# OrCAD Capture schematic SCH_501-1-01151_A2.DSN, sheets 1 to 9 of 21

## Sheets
1 P01_COVER_PAGE
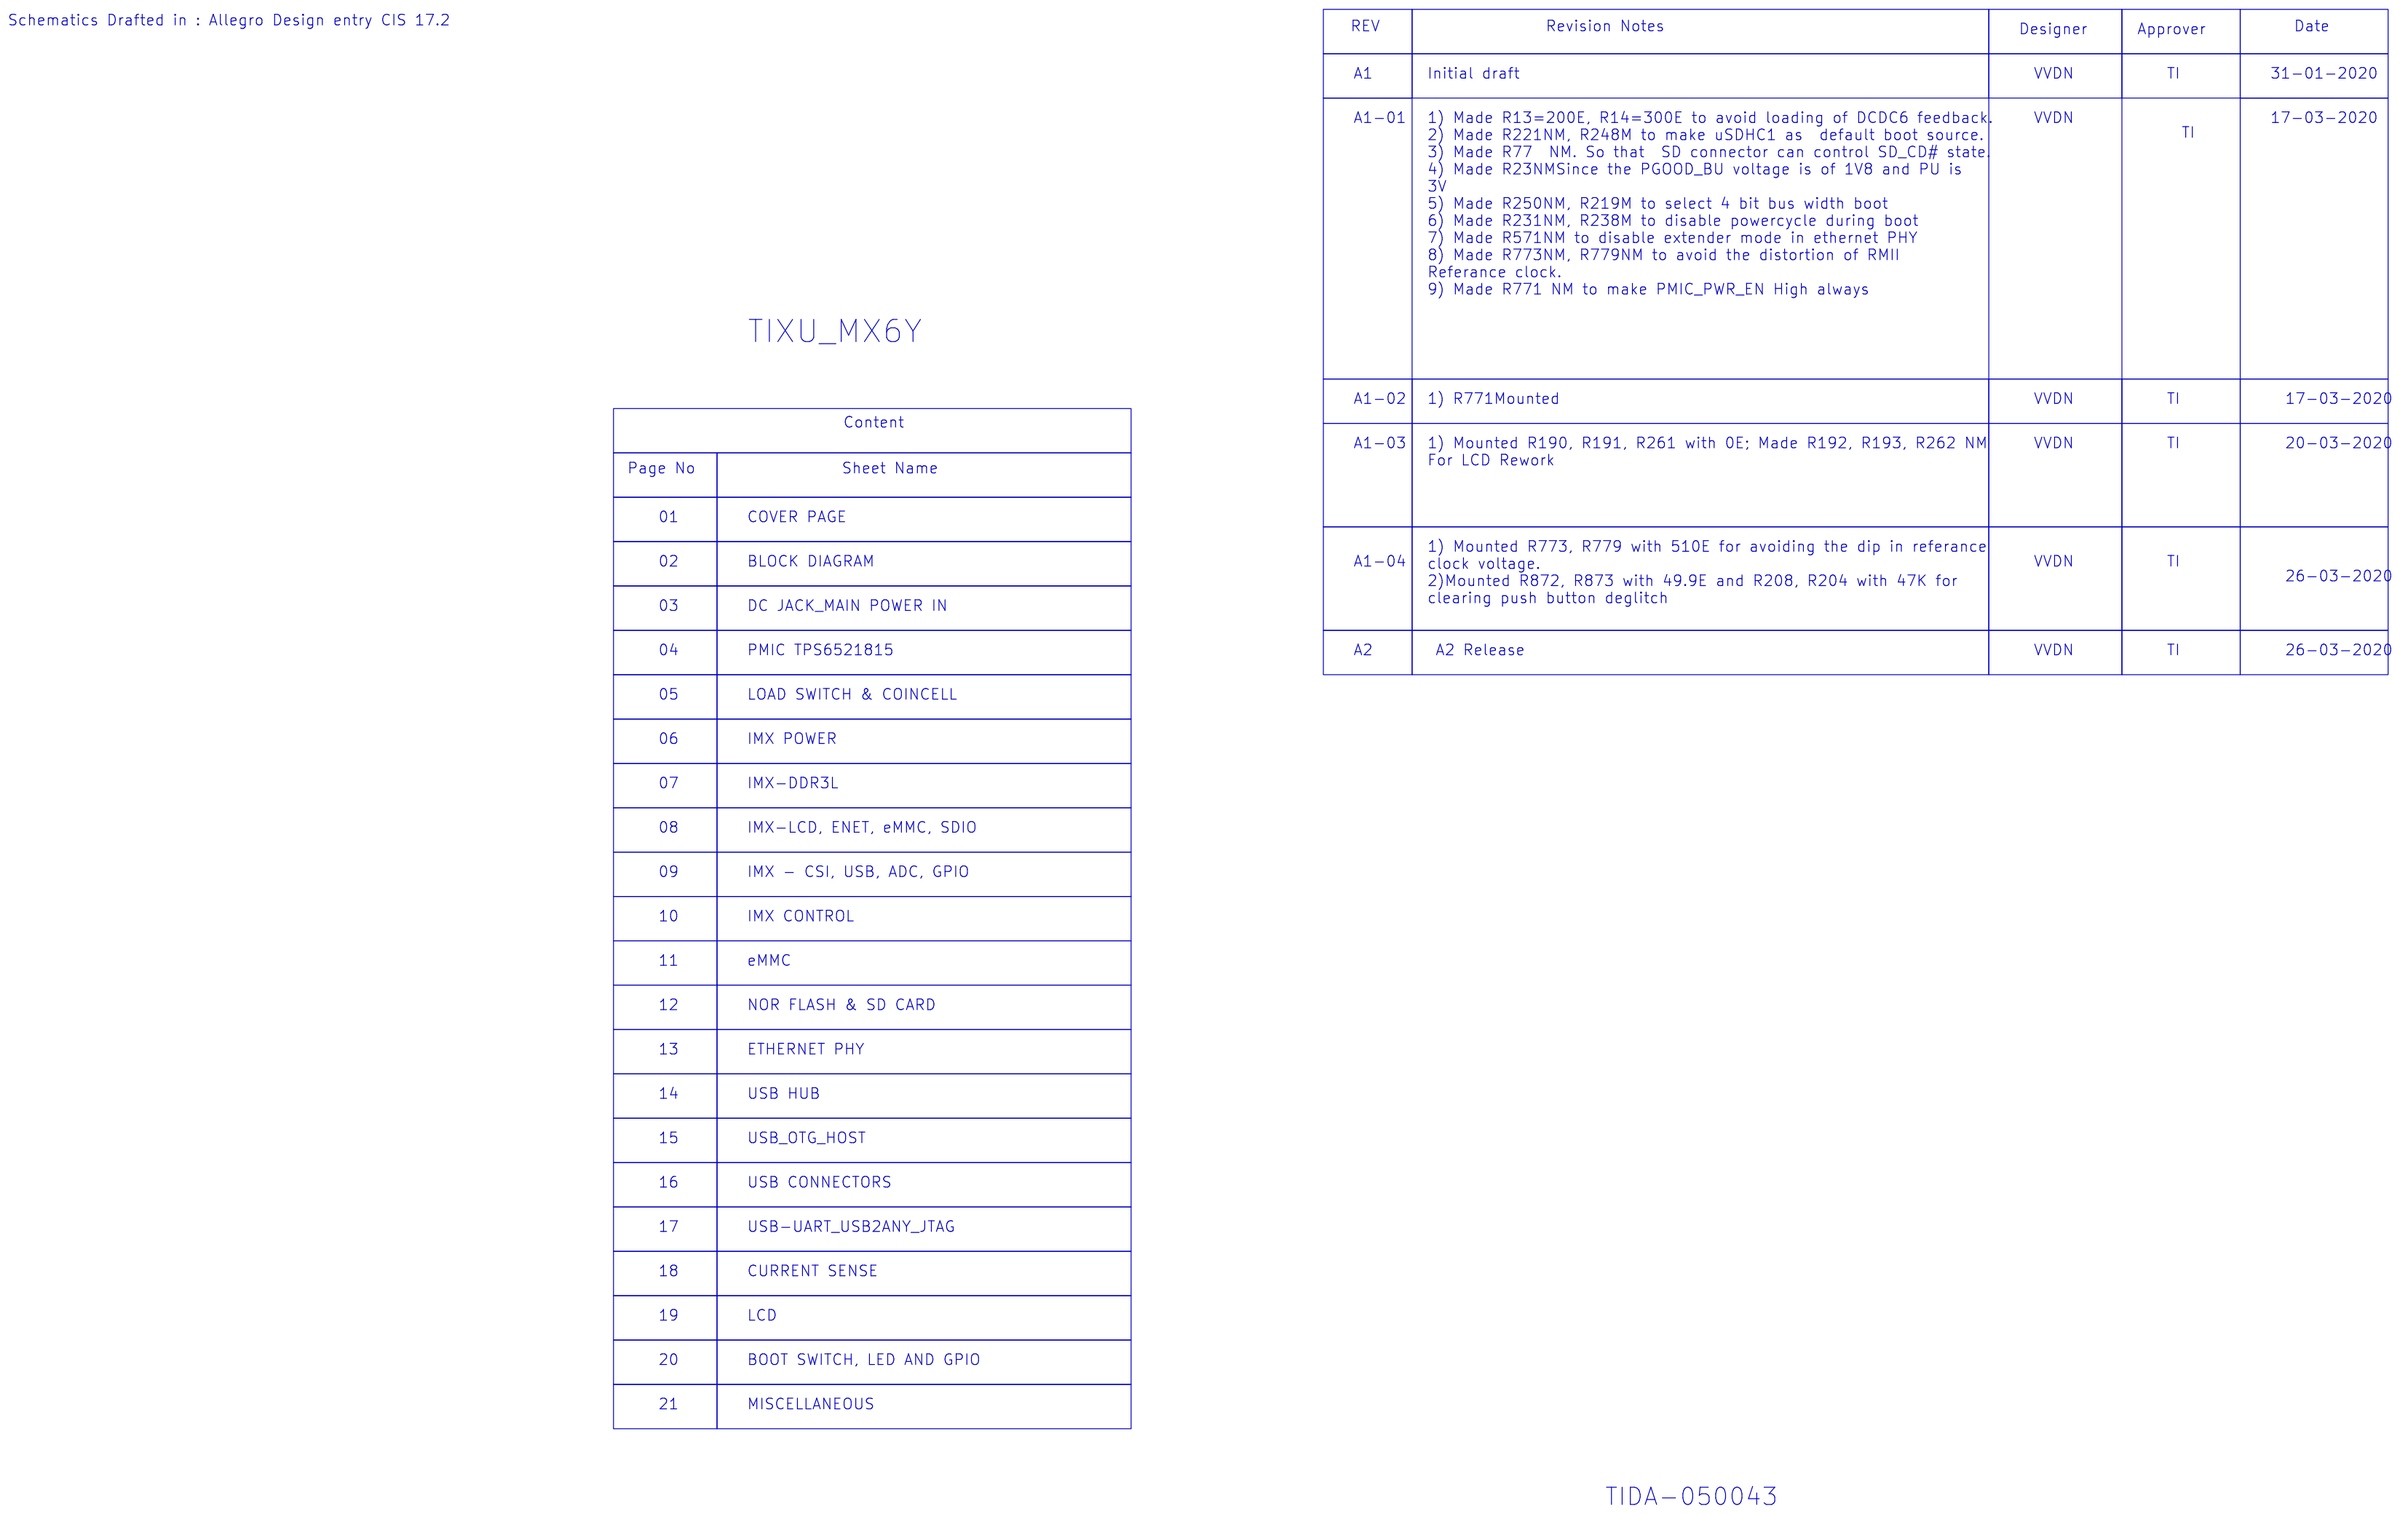
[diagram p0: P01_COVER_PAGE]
2 P02_BLOCK_DIAGRAM
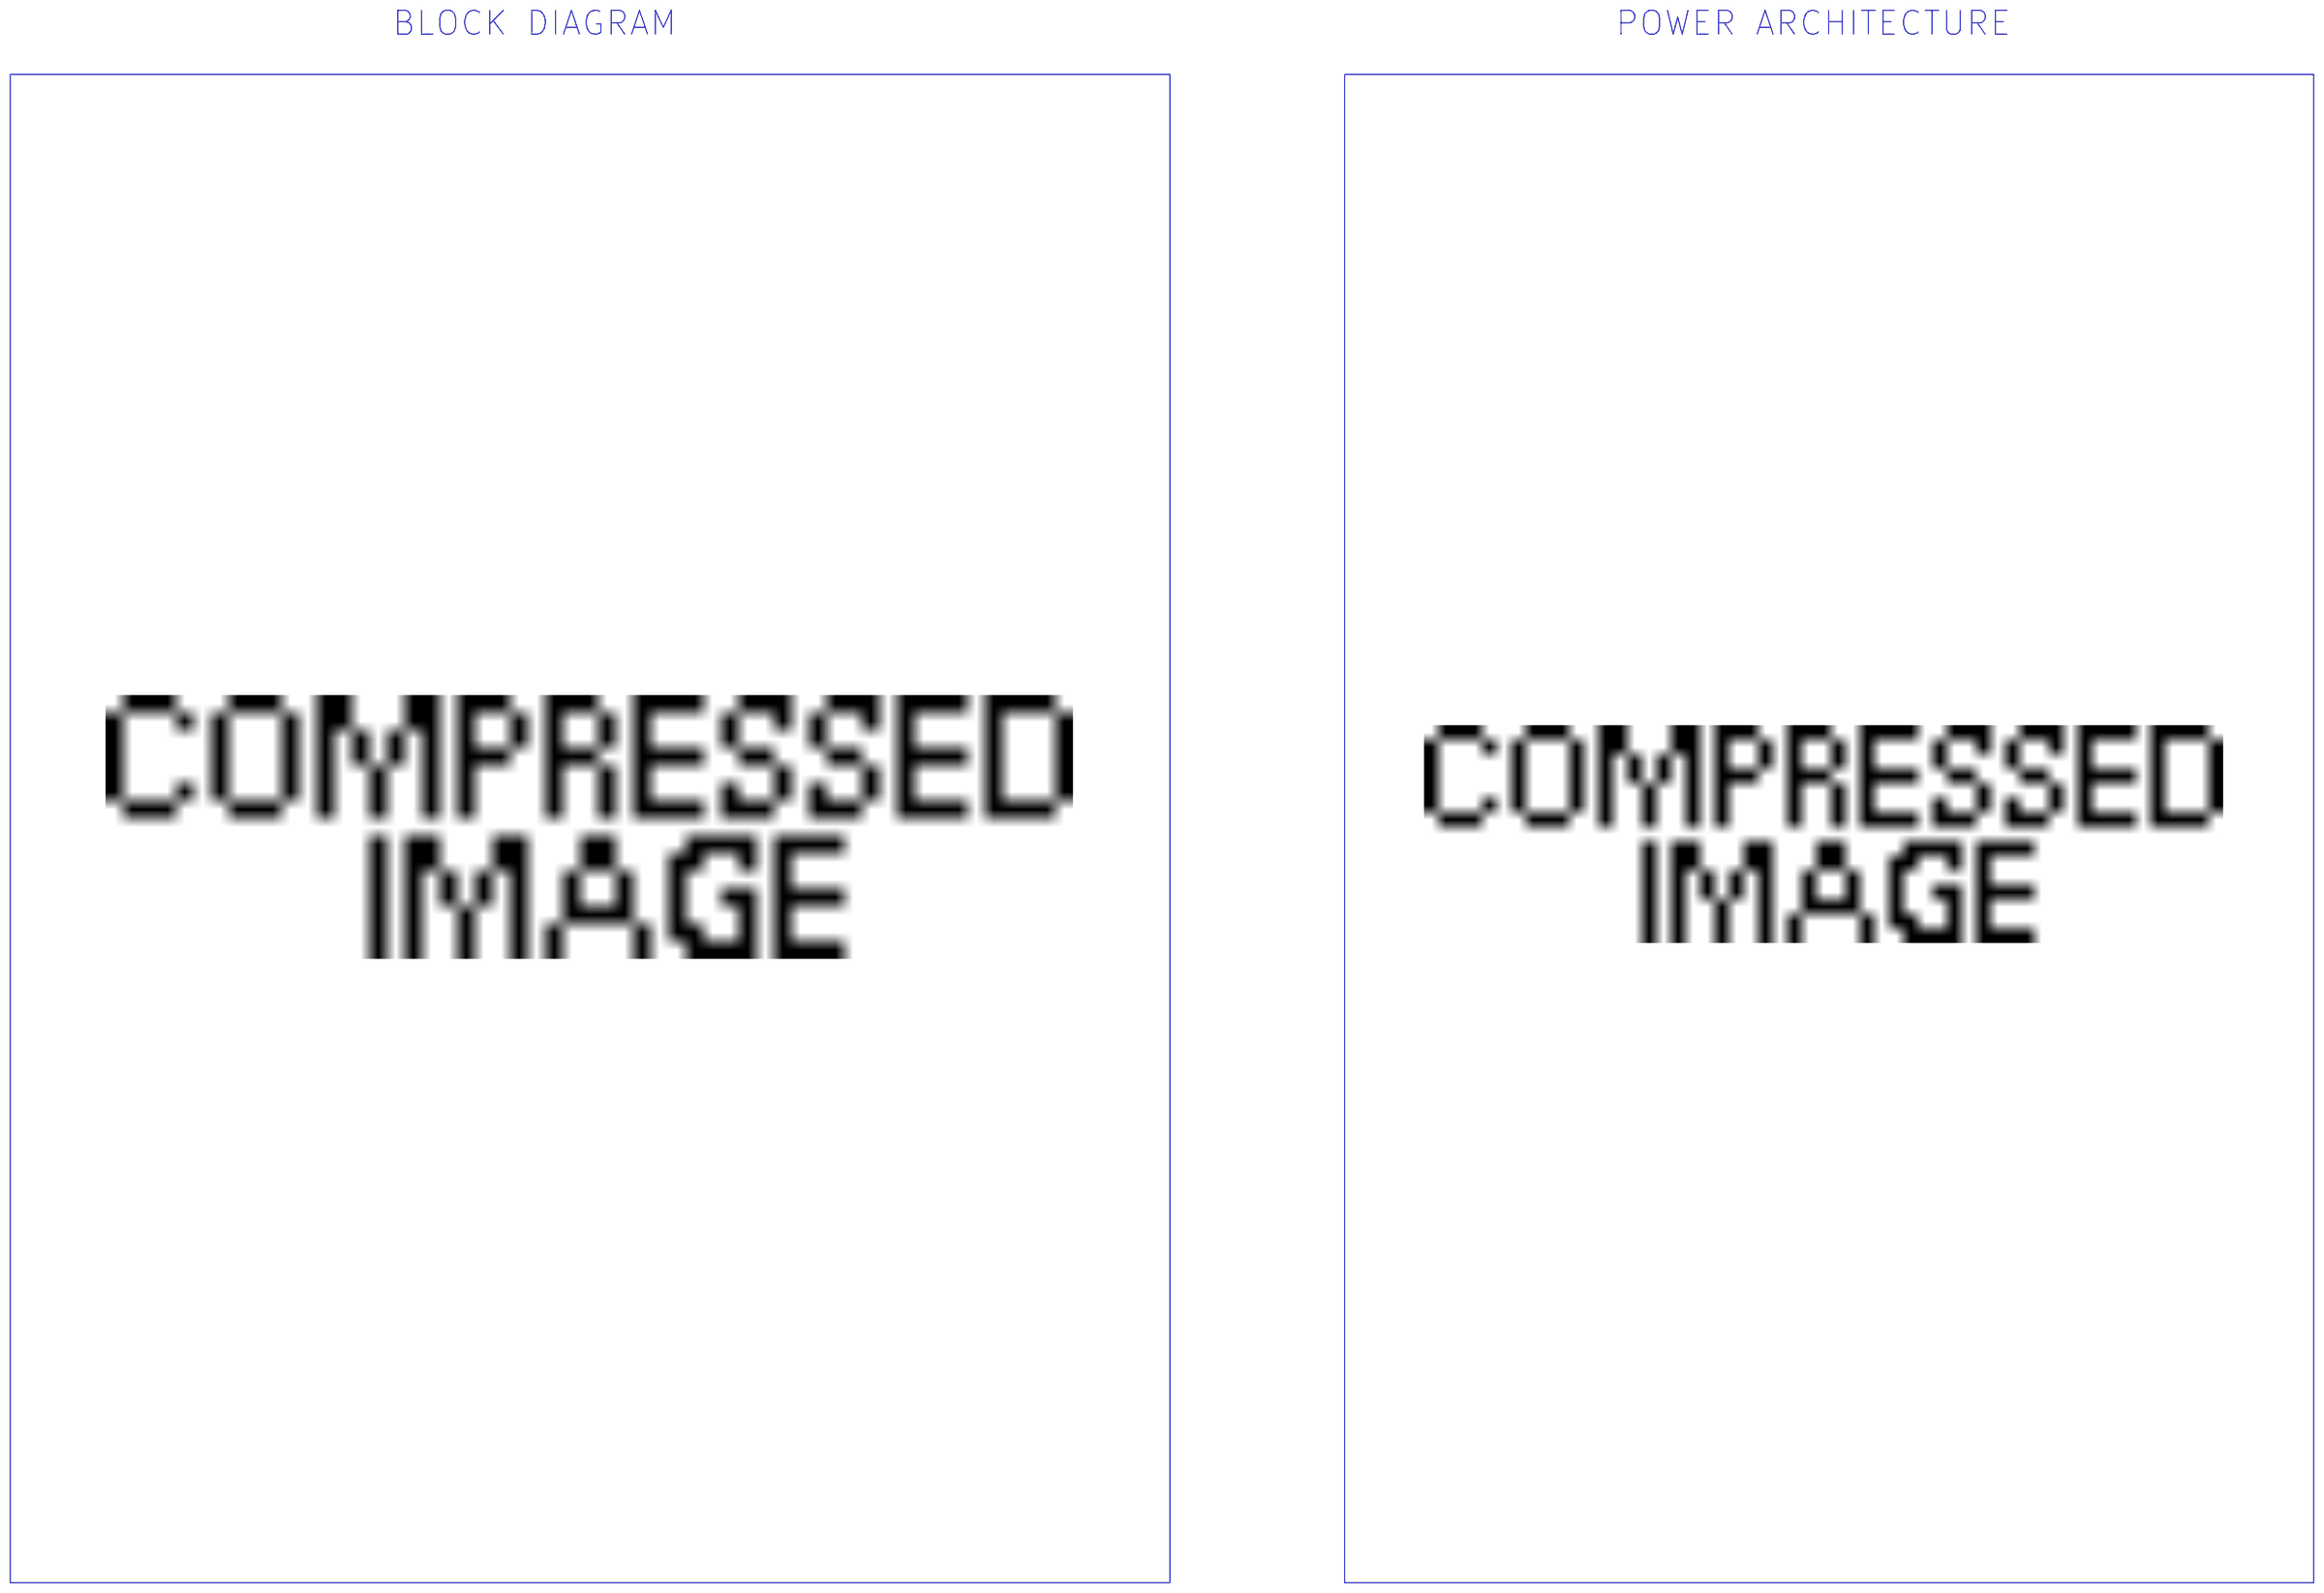
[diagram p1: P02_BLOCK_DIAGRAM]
3 P03_DC JACK_MAIN POWER IN: size A3
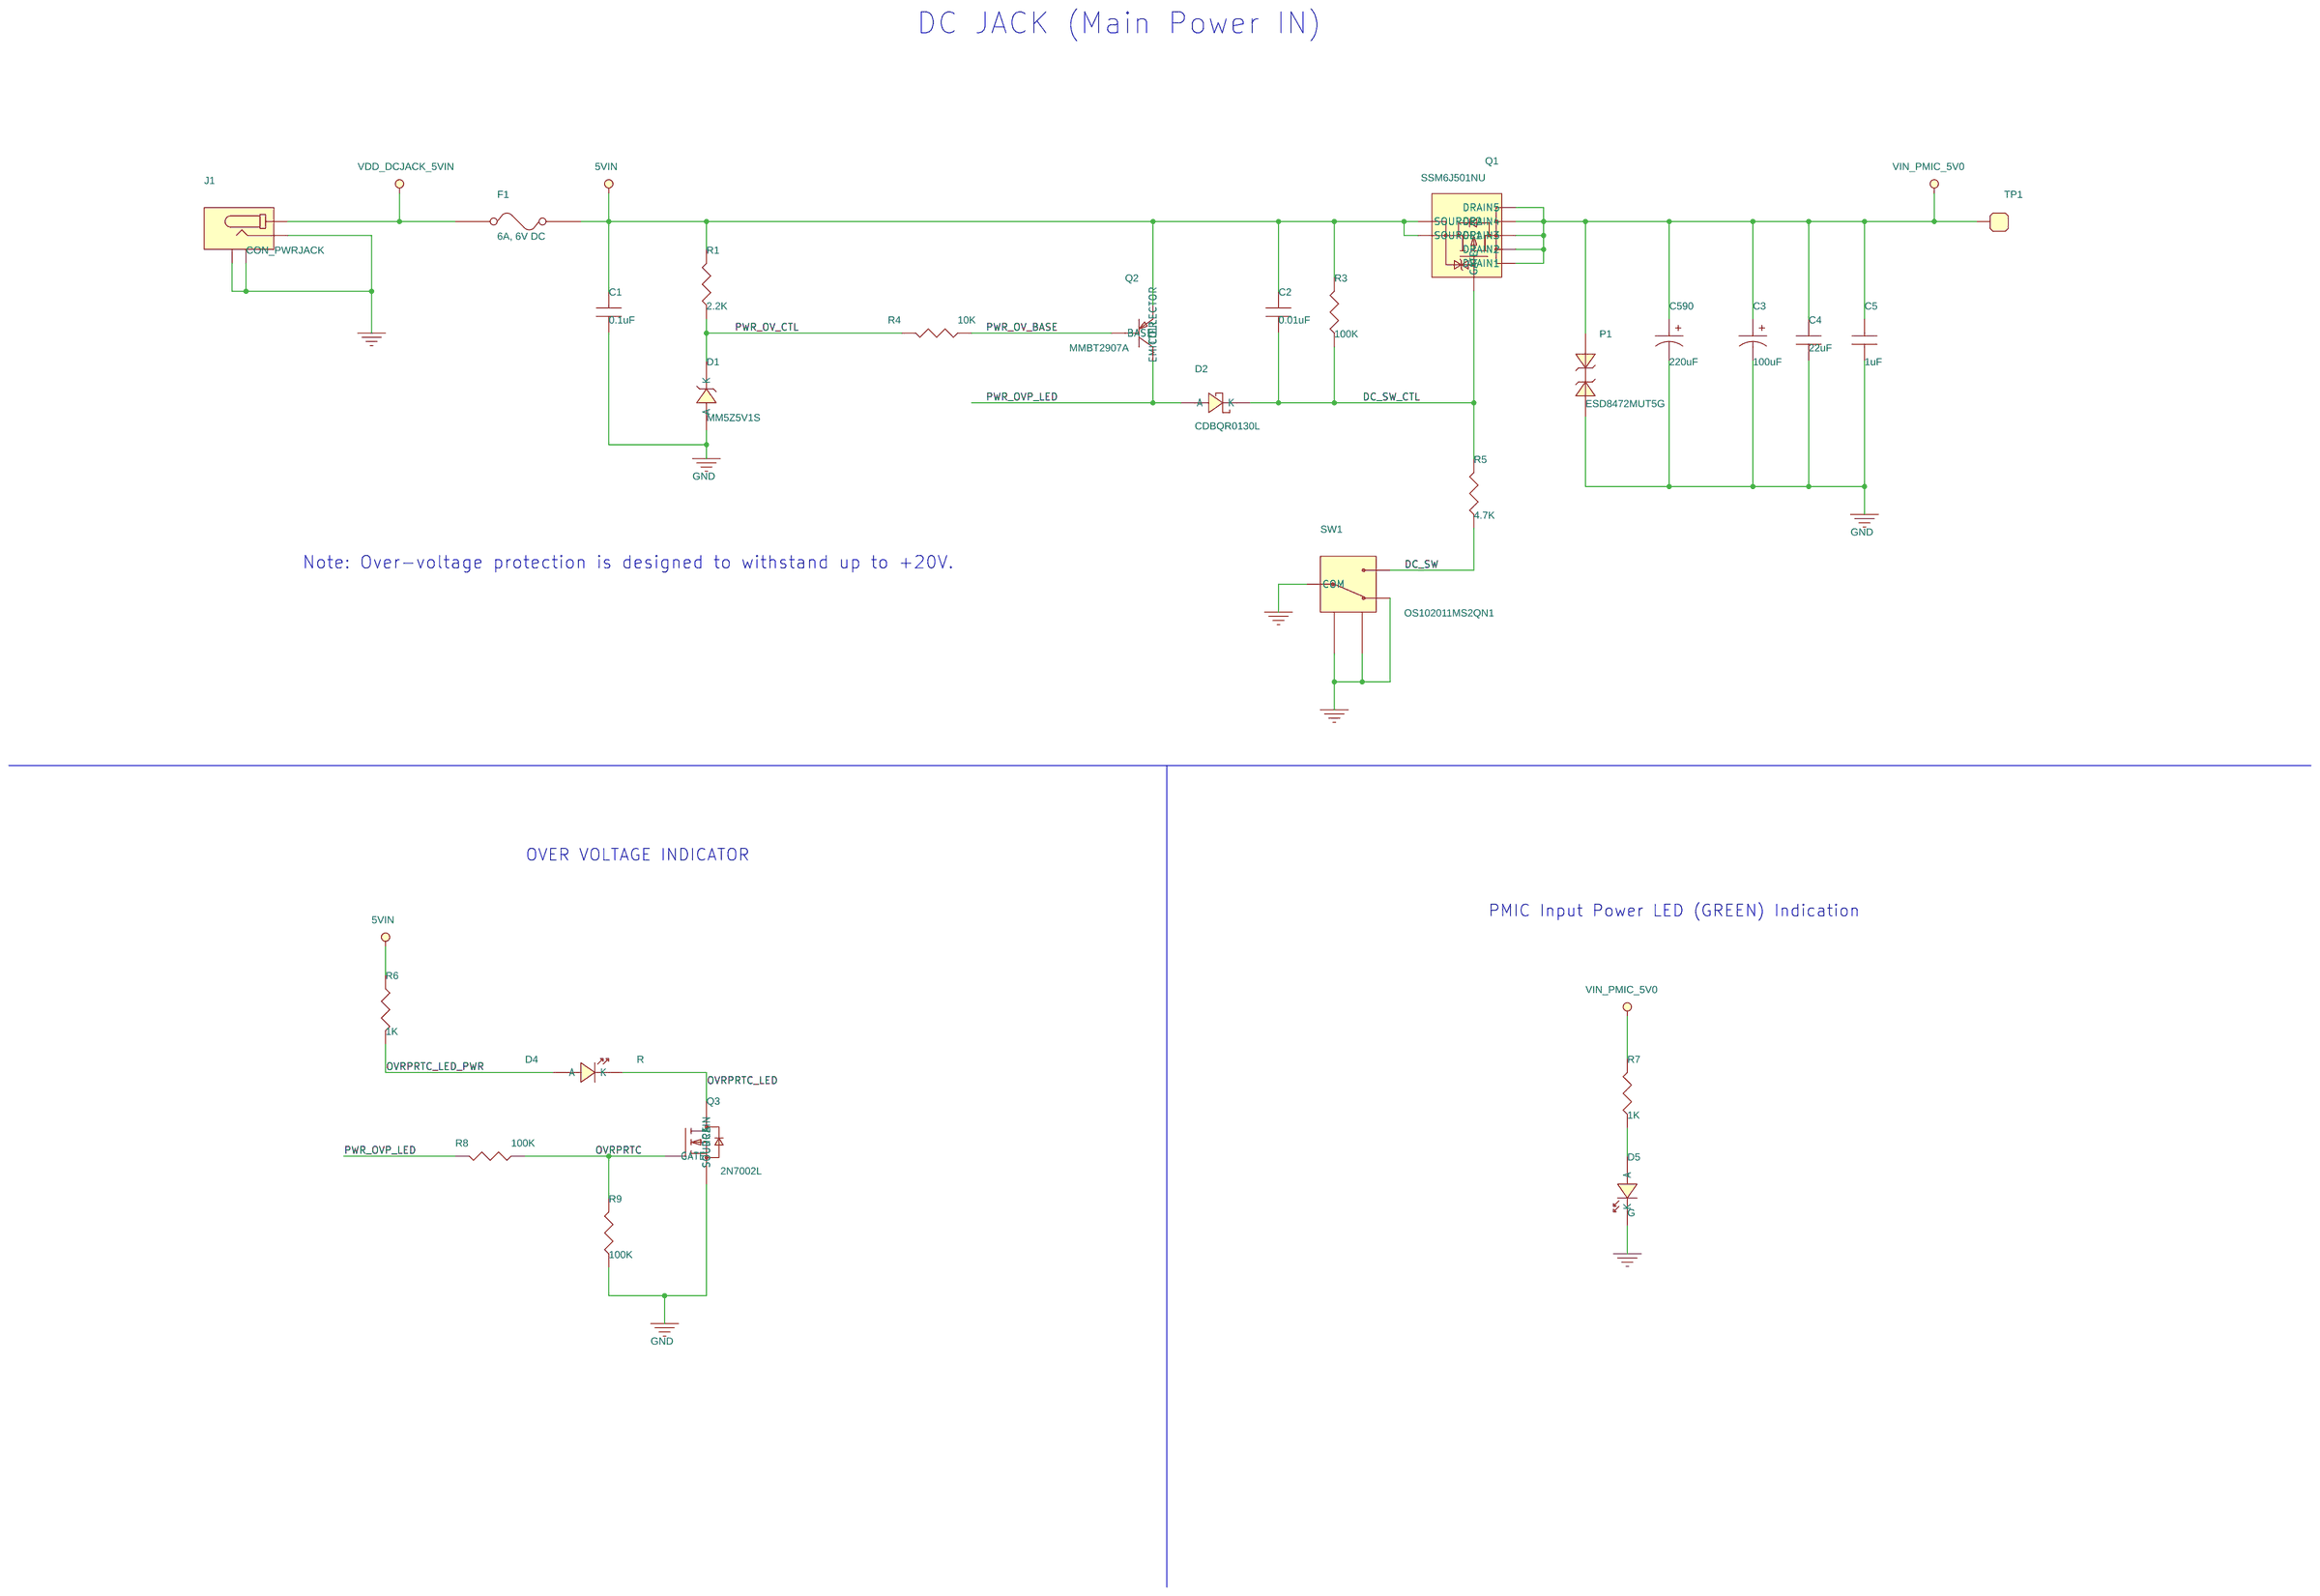
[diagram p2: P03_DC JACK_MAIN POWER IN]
4 P04_PMIC TPS6521815: size A3
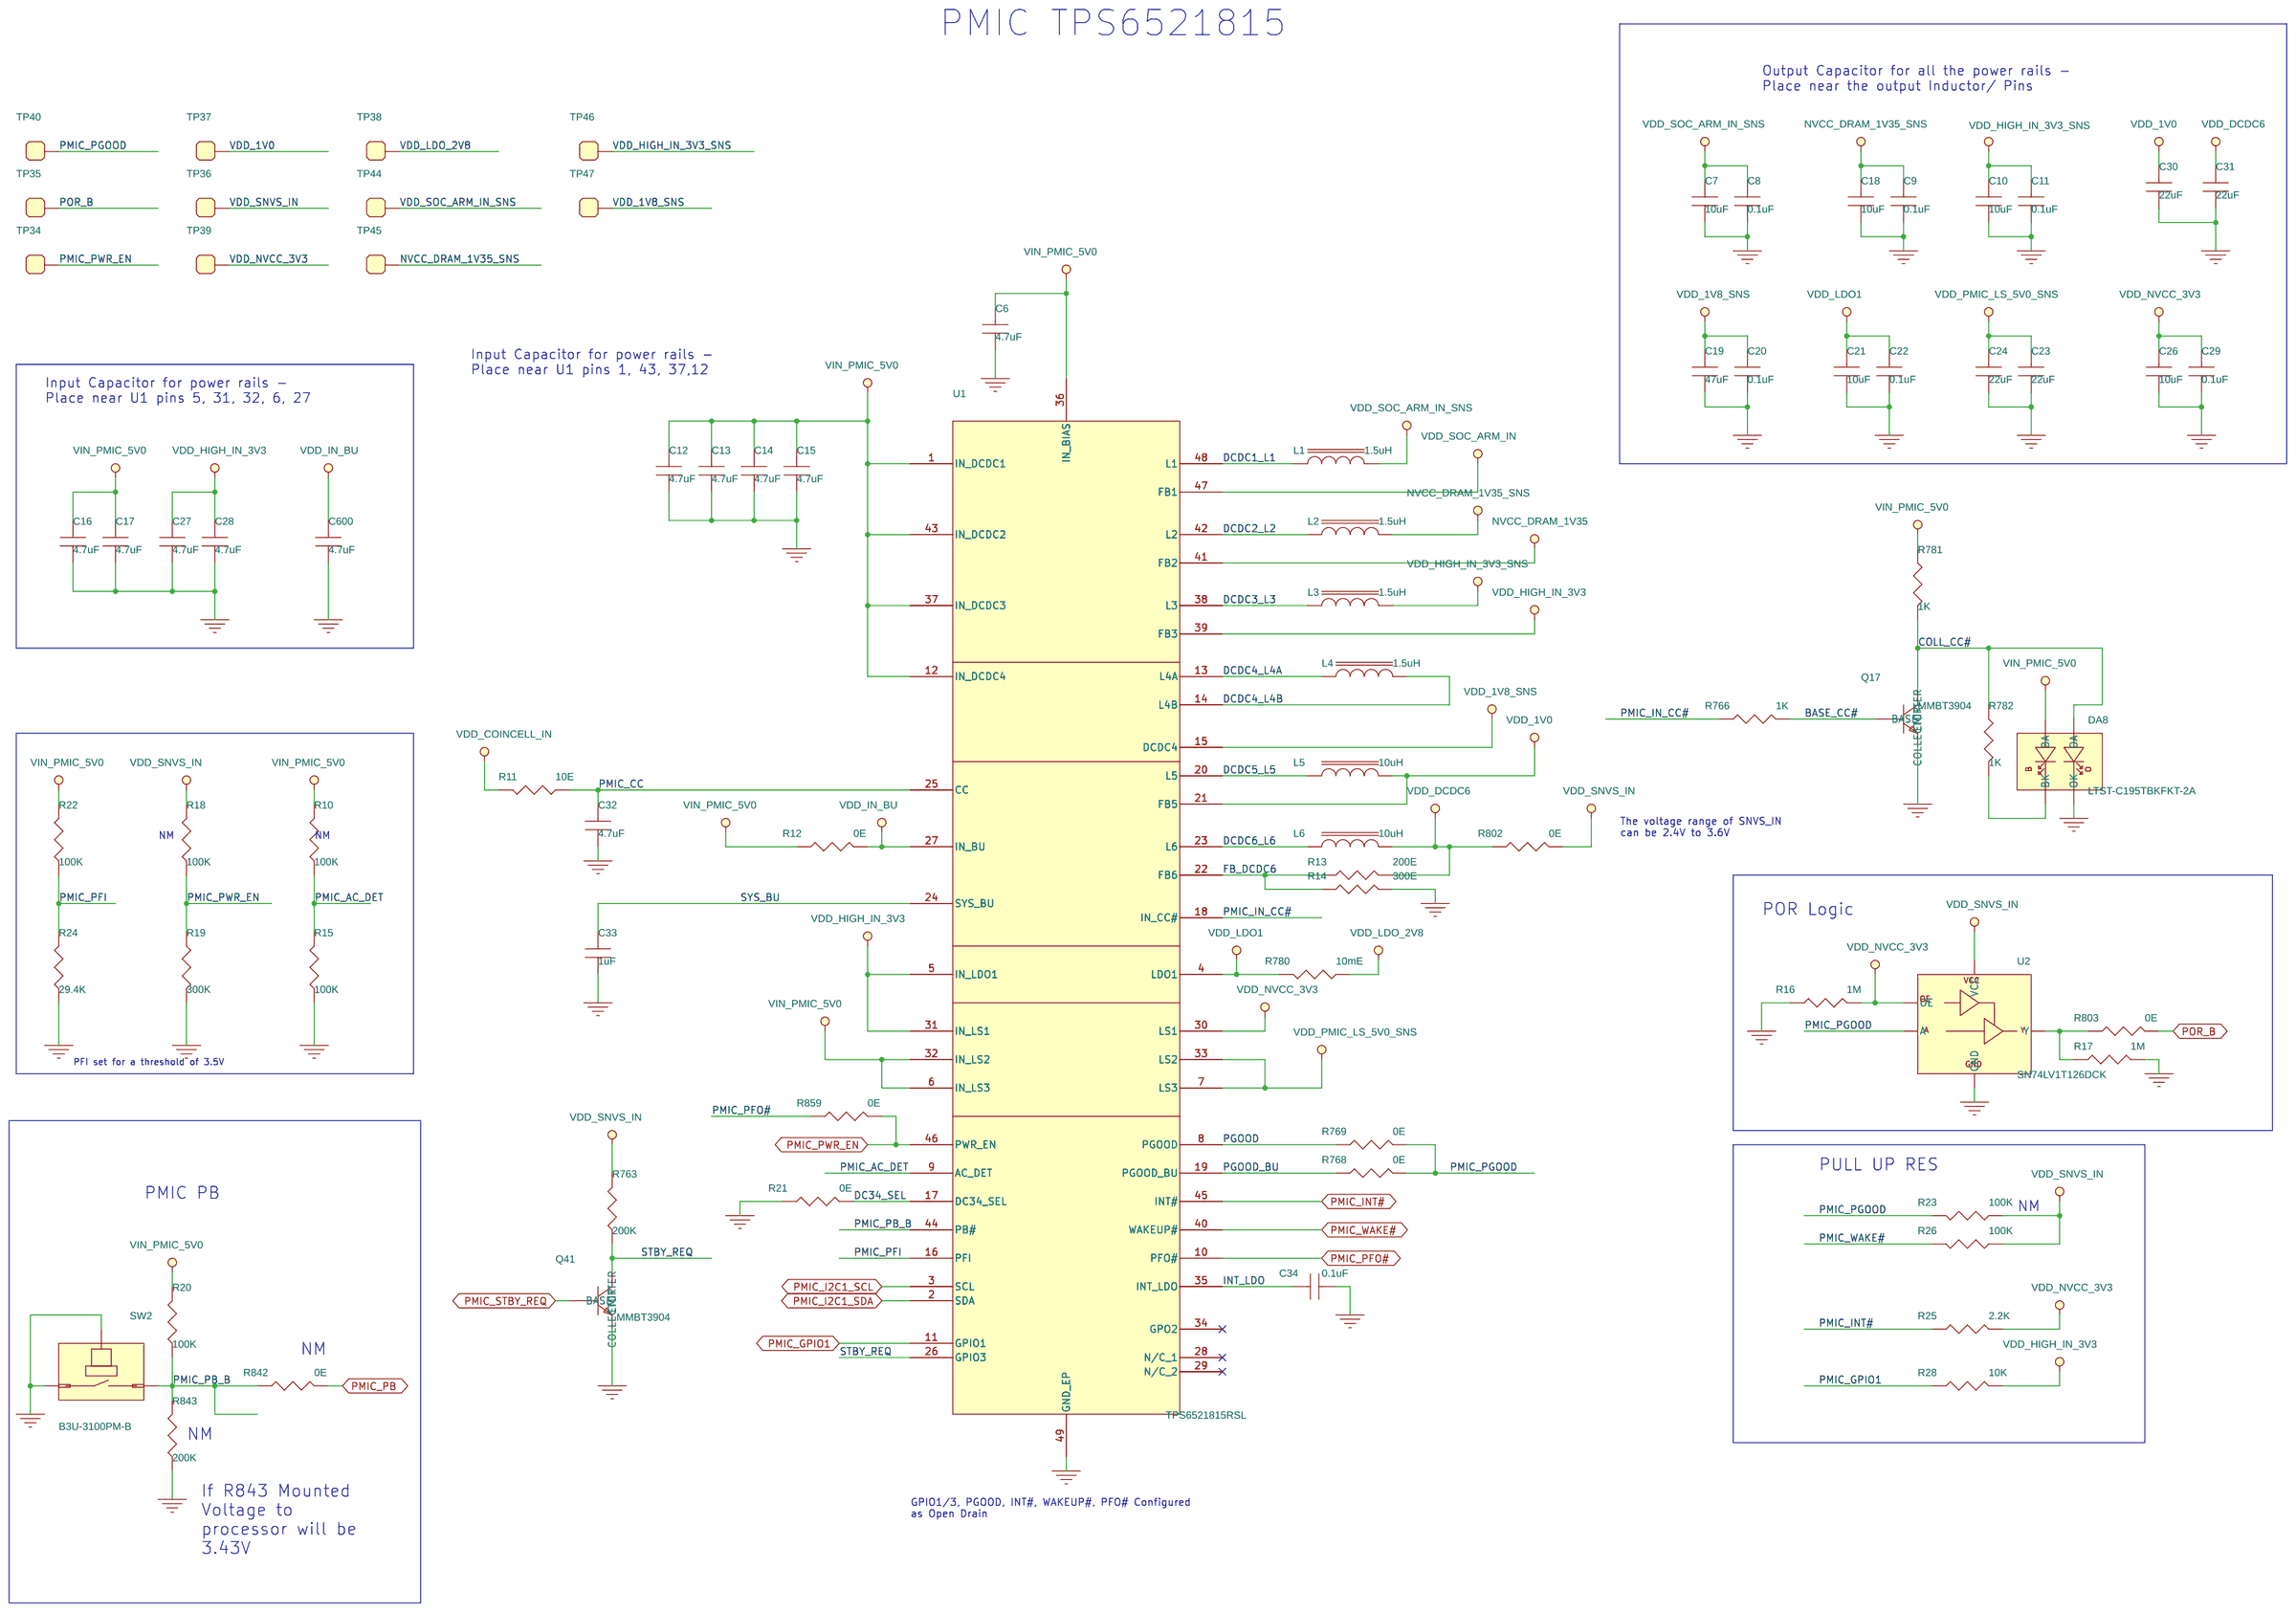
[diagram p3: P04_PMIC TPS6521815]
5 P05_SWITCHES_COIN CELL_WD: size A3
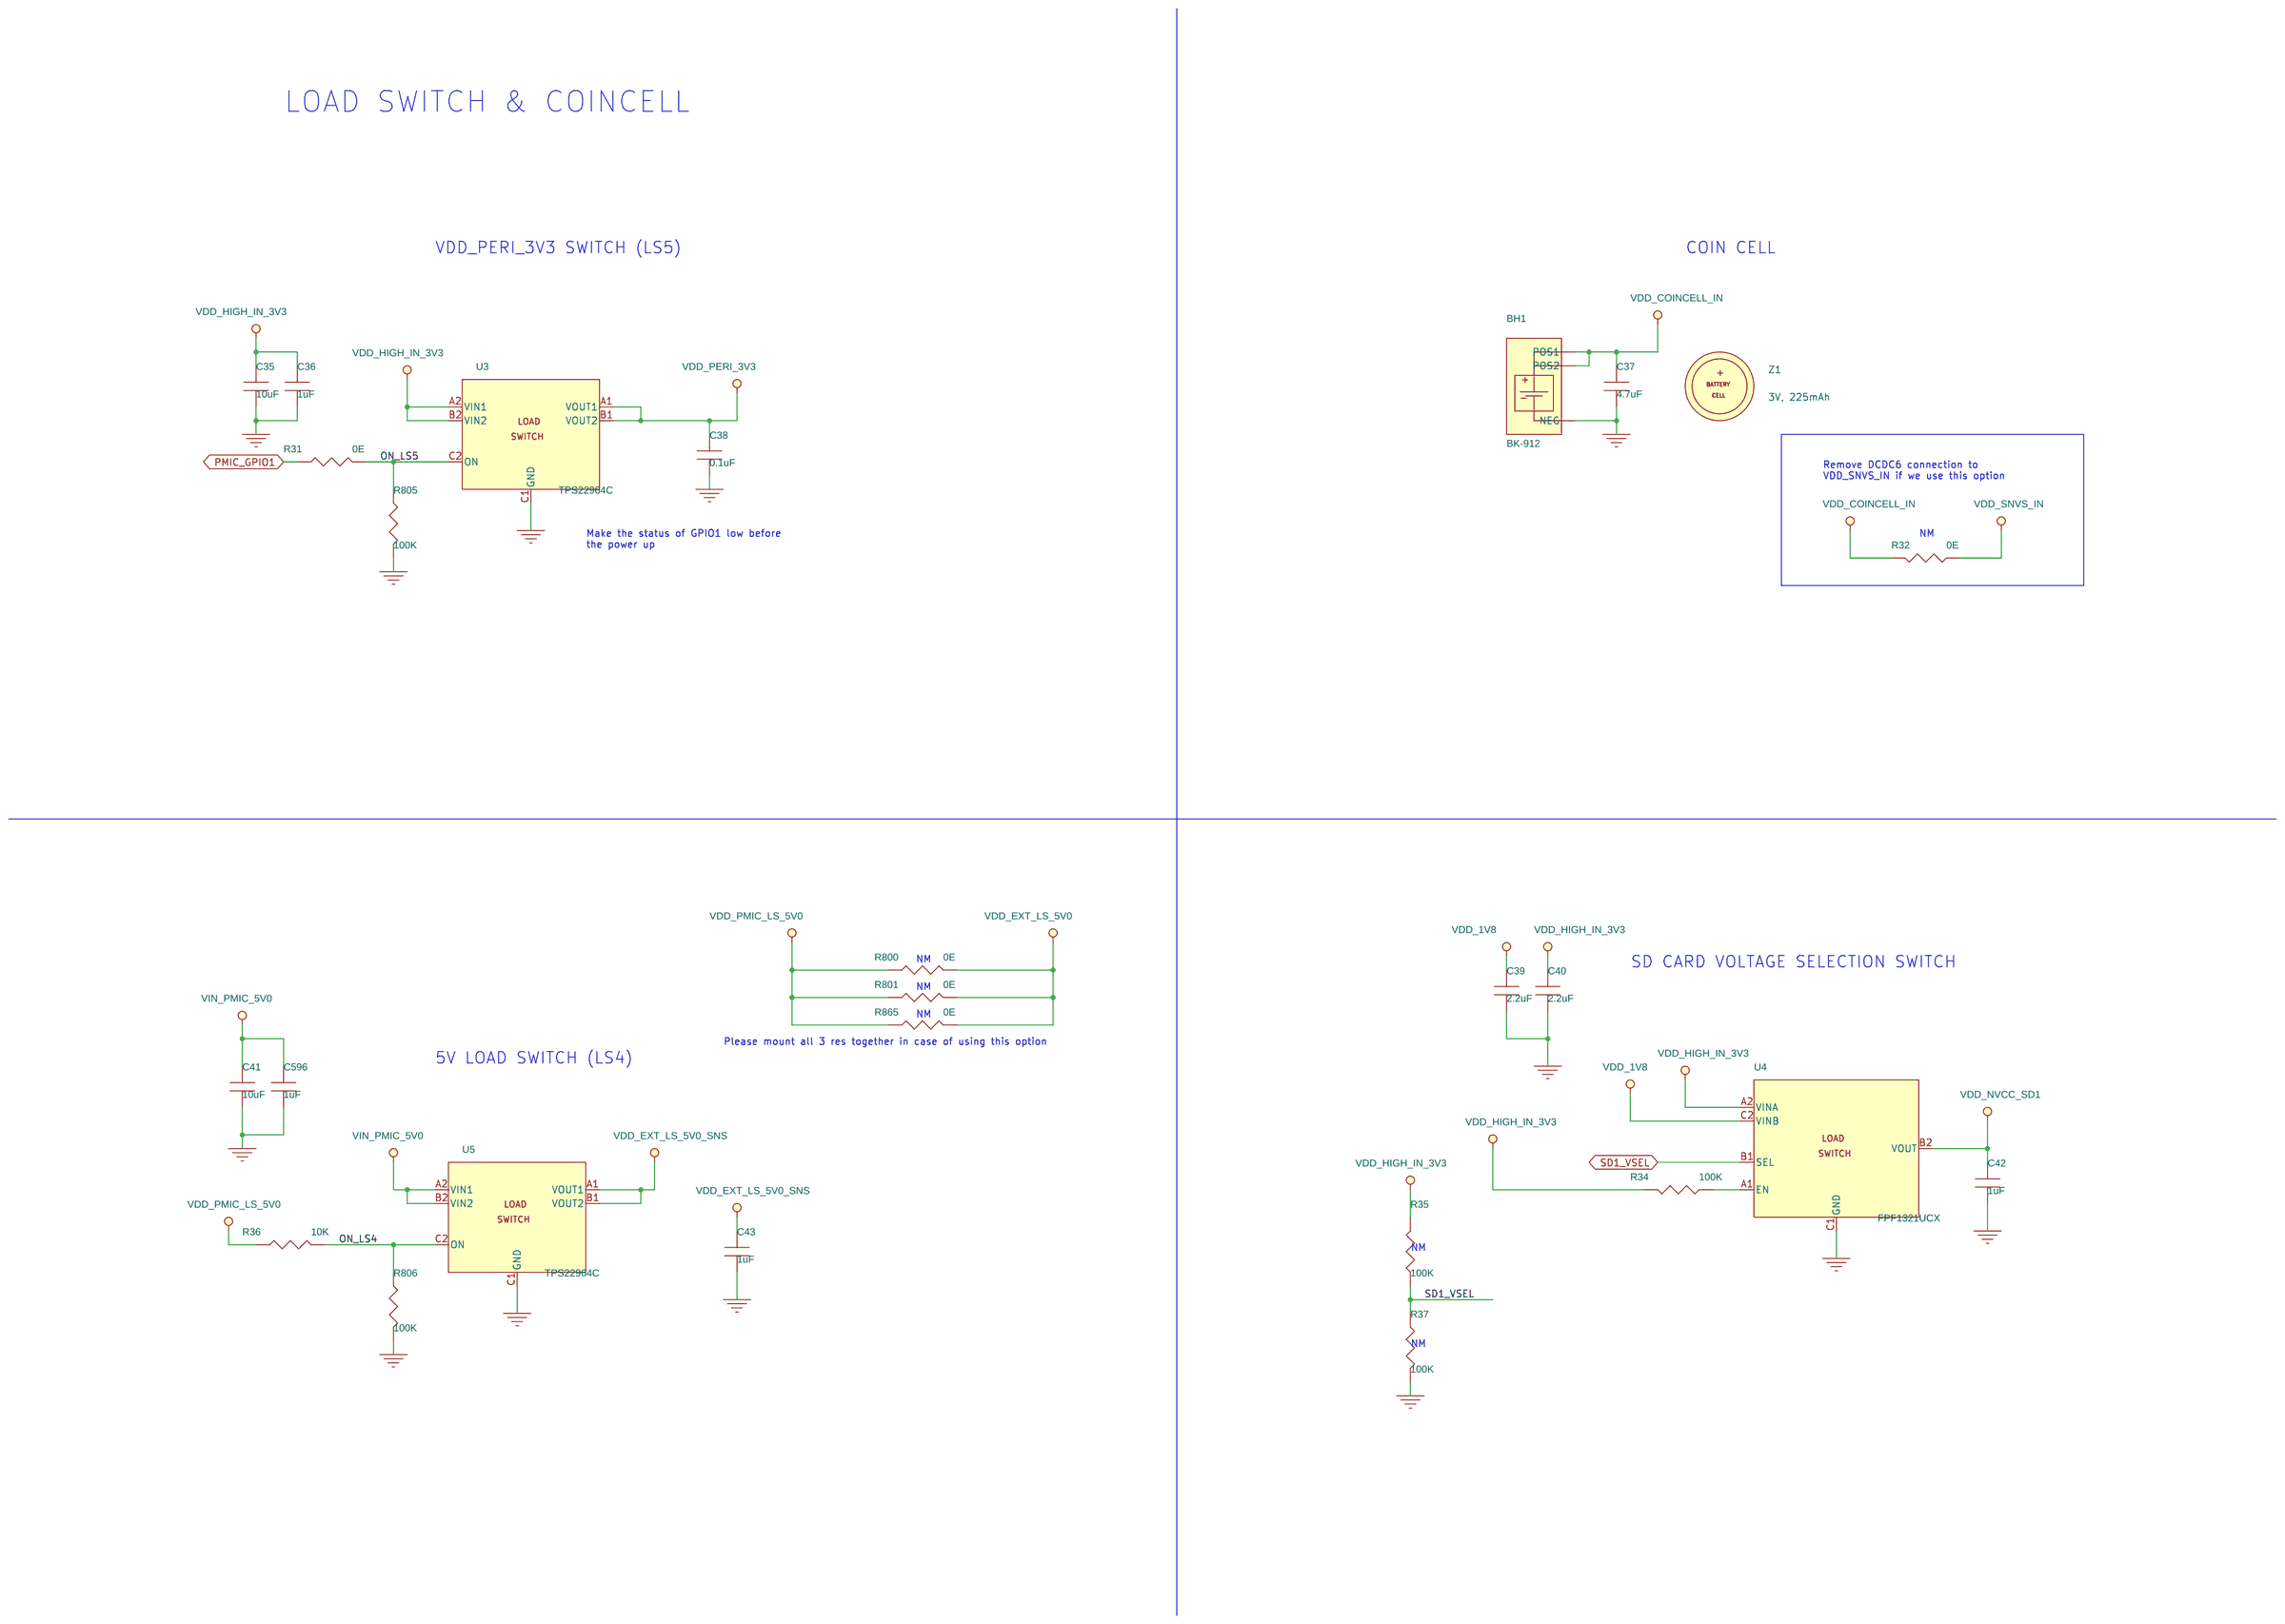
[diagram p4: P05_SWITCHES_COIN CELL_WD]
6 P06_IMX POWER: size A3
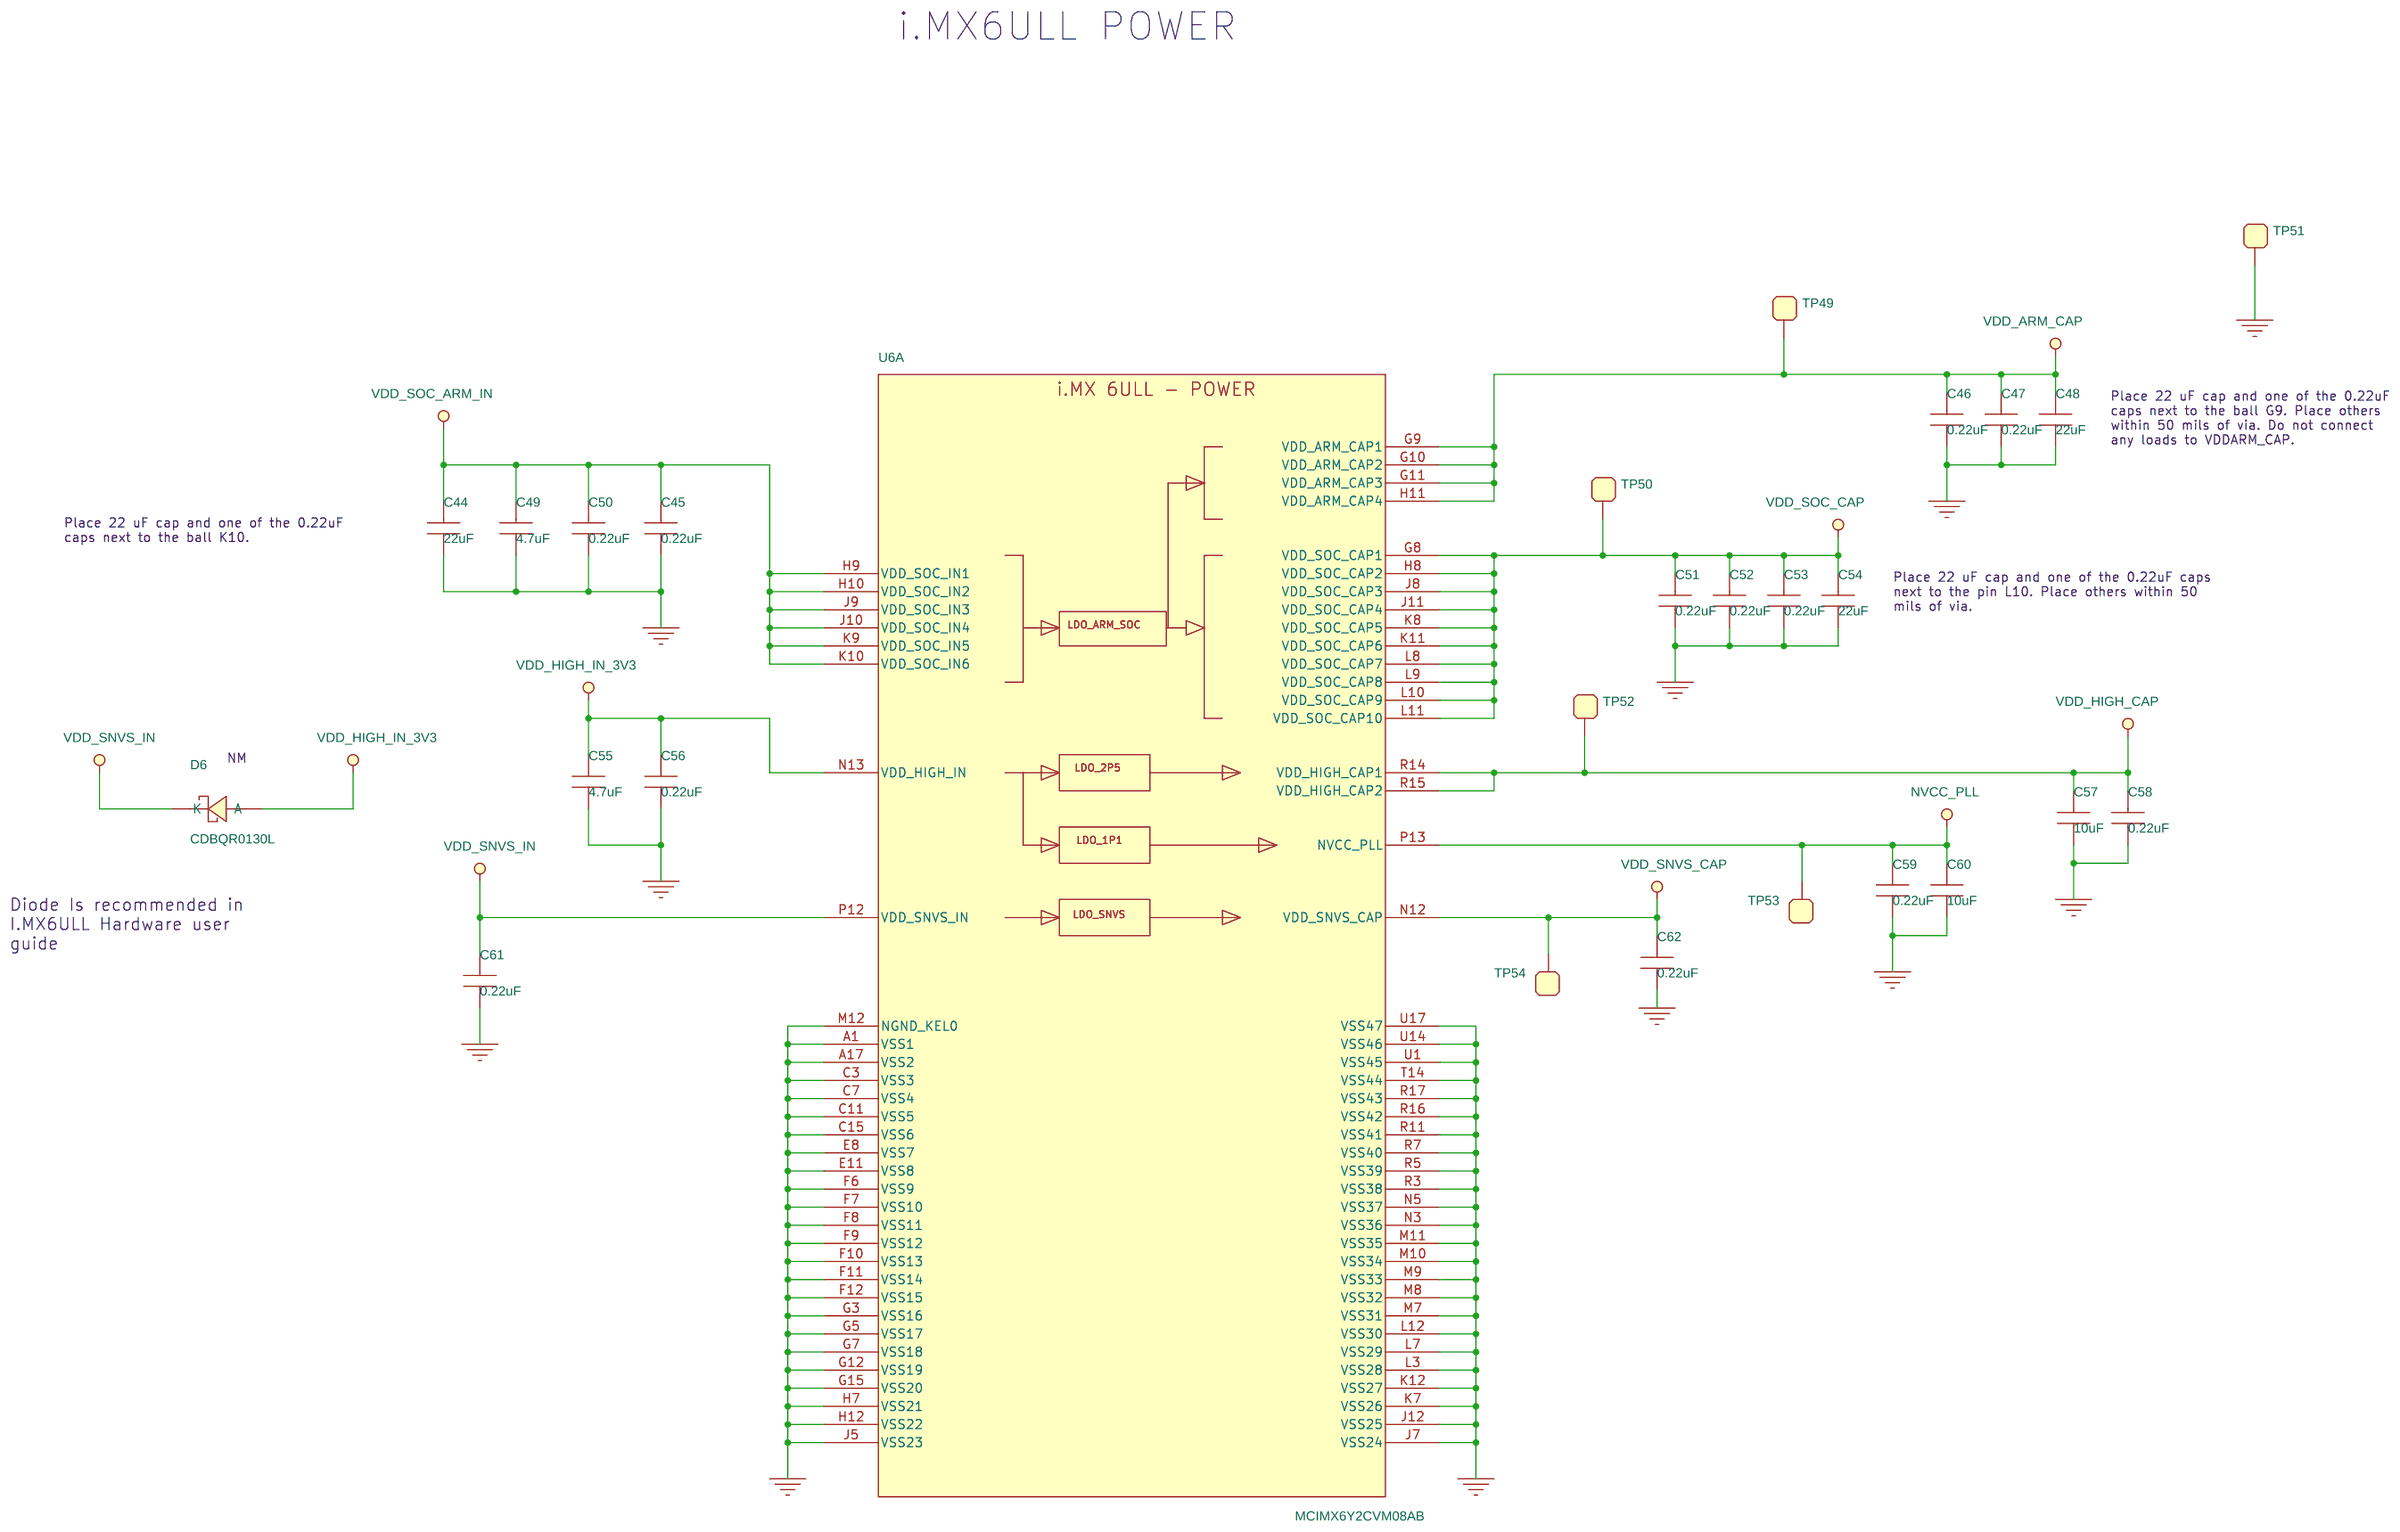
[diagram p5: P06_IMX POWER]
7 P07_IMX-DDR3L: size A3
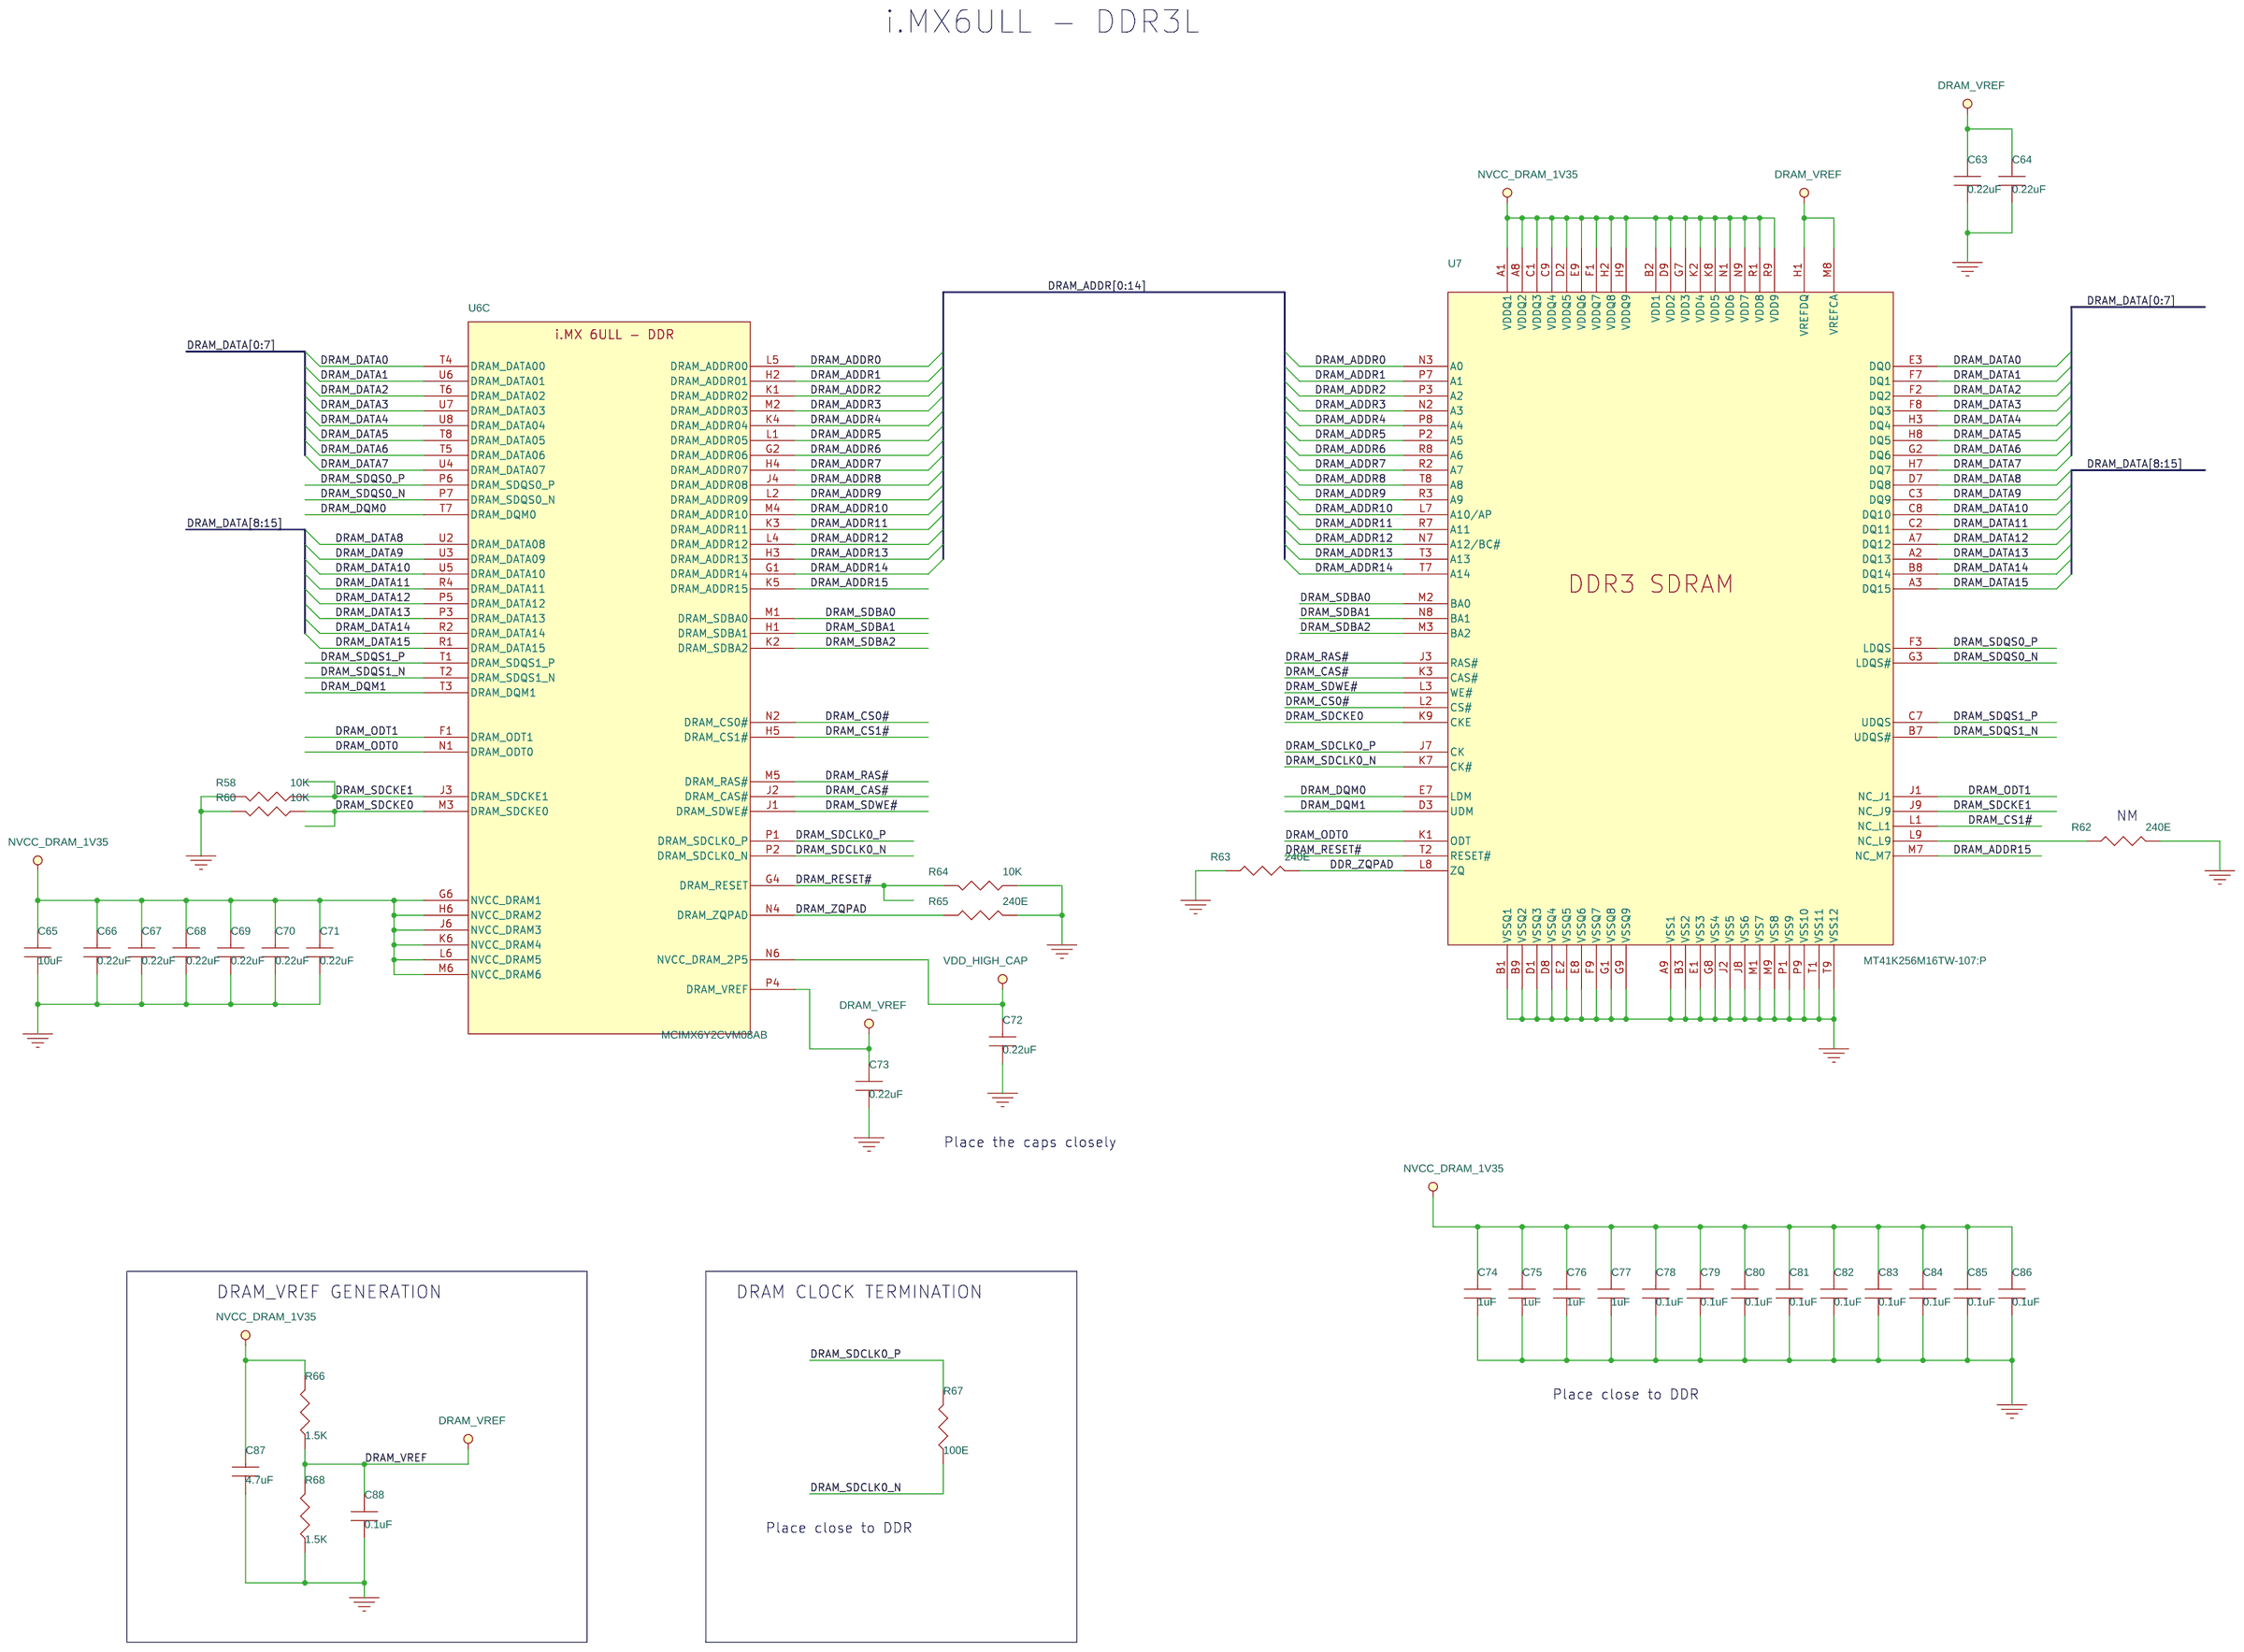
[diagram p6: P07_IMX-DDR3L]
8 P08_IMX-LCD,ENET,eMMC,SDIO: size A3
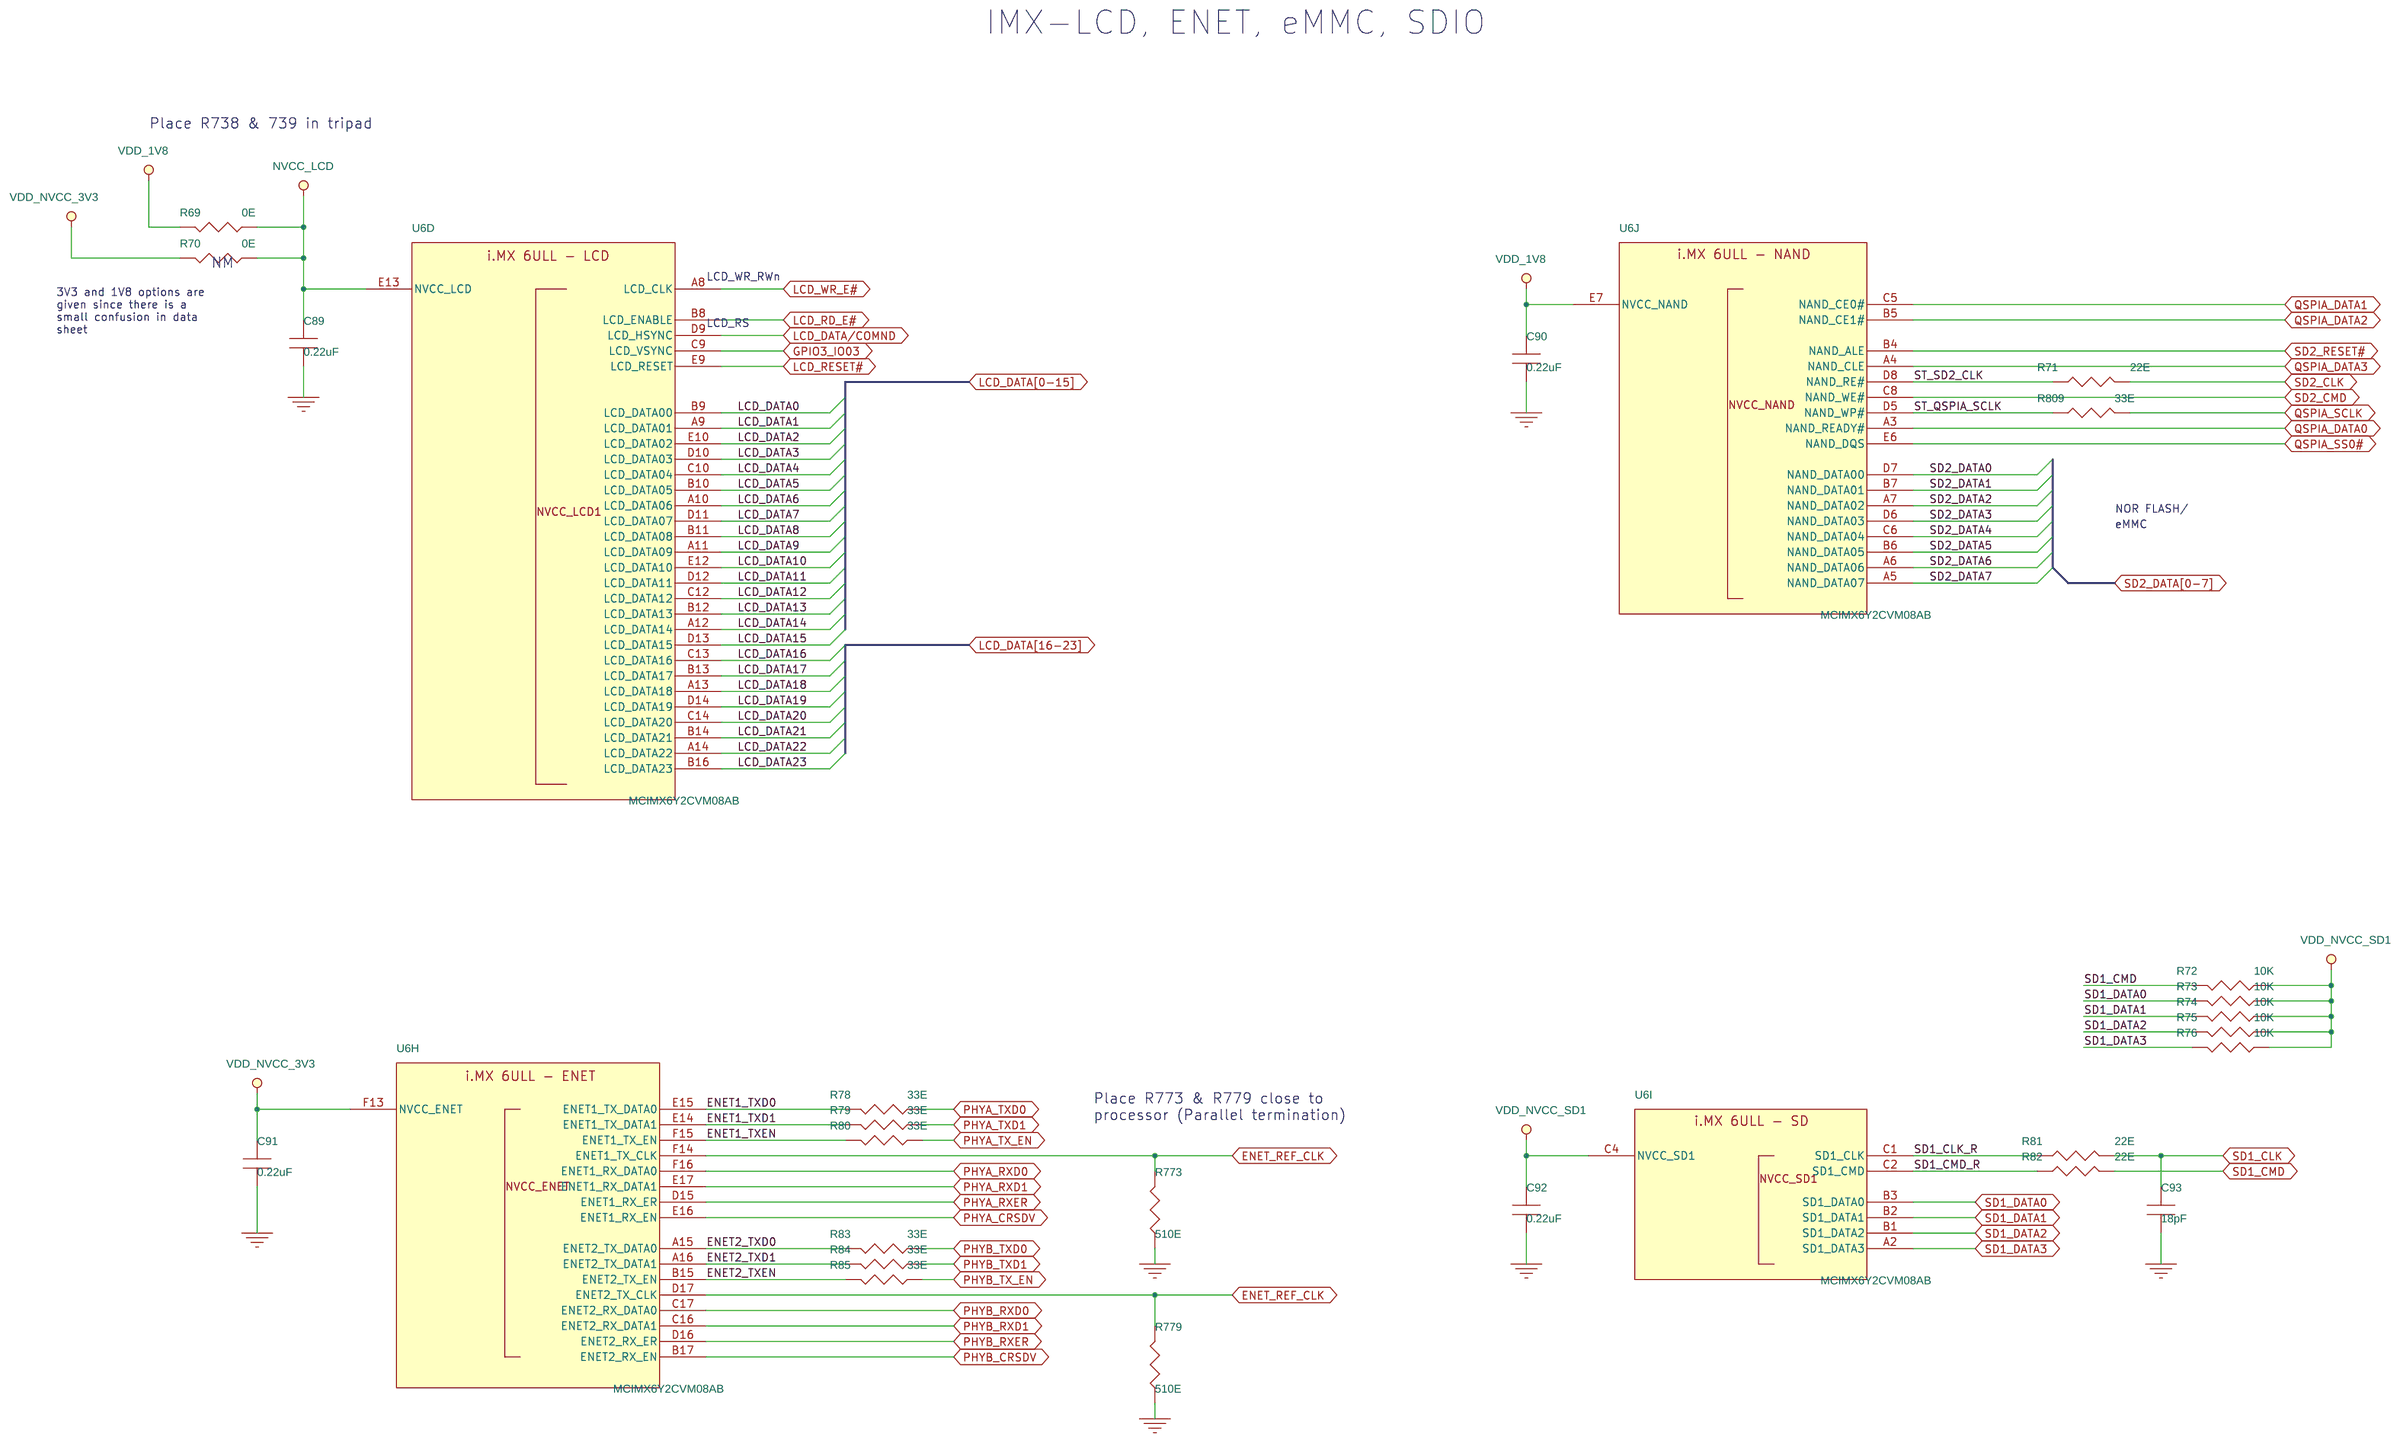
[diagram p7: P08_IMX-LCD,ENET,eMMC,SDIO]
9 P09_IMX - CSI,USB,ADC,GPIO: size A3
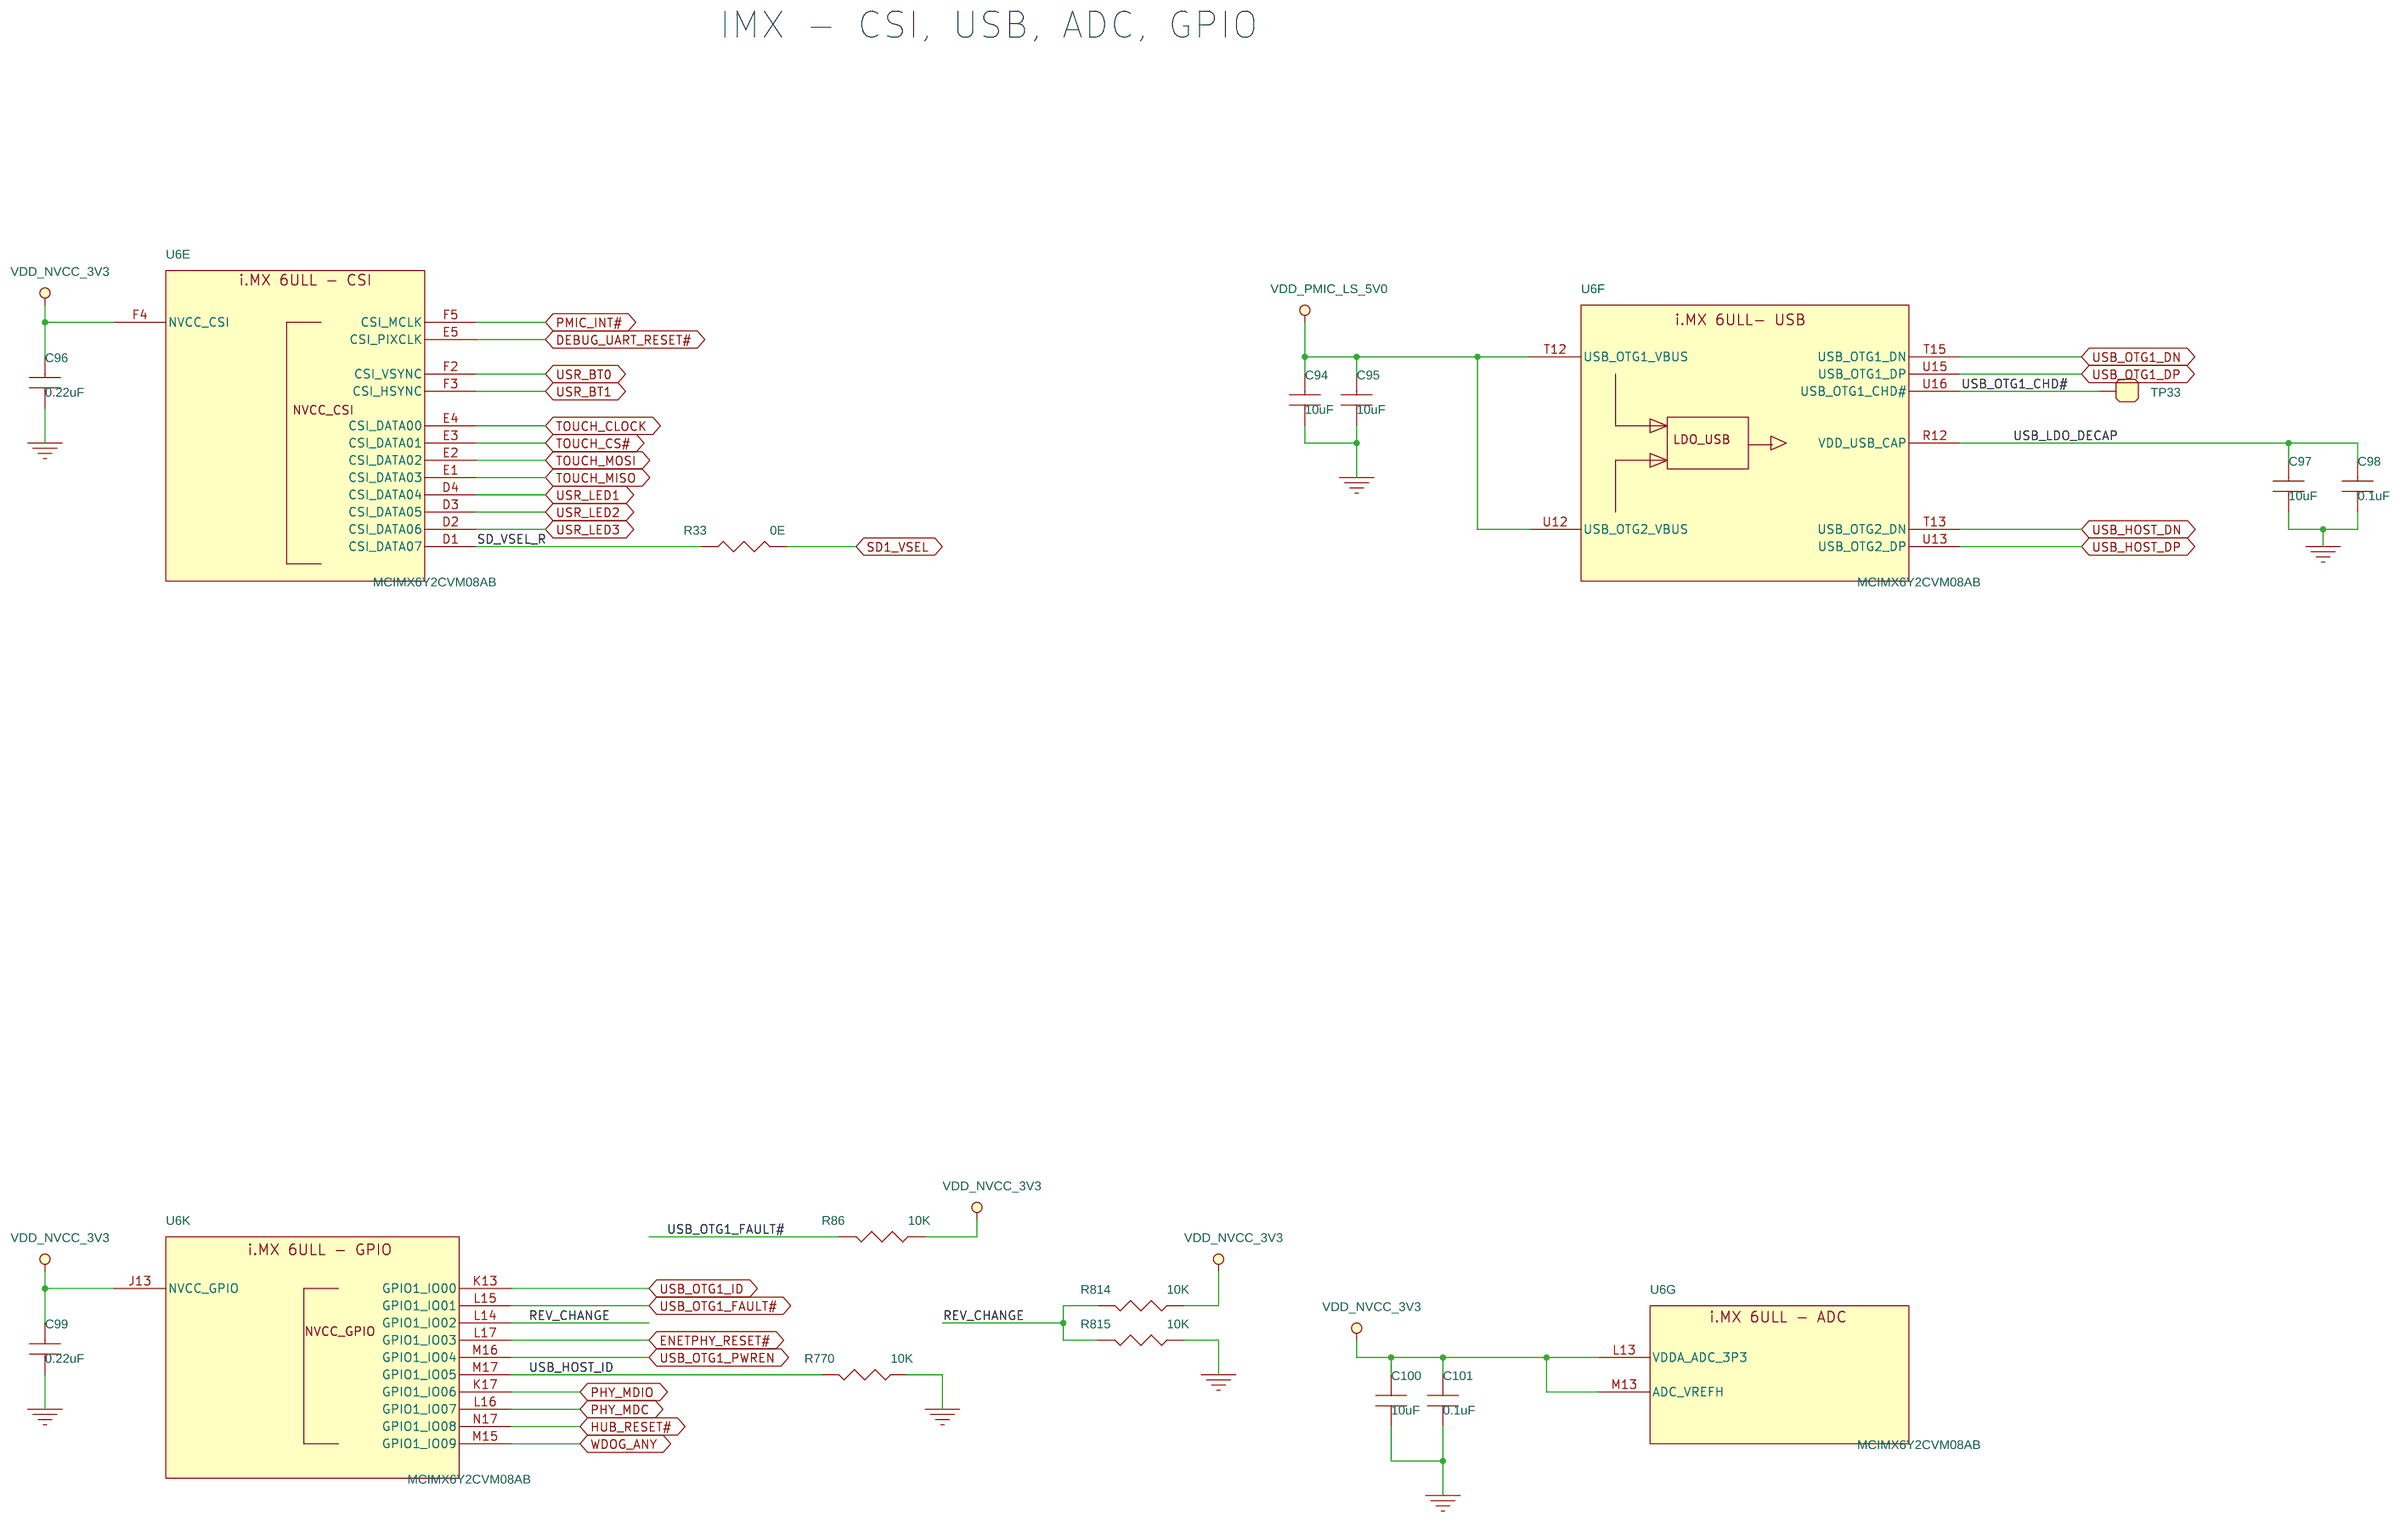
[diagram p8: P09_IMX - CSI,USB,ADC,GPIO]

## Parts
sheet P03_DC JACK_MAIN POWER IN
C1  0.1uF  [0402]
C2  0.01uF  [0402]
C3  100uF  [TCAP_CASED]
C4  22uF  [0603]
C5  1uF  [0402]
C590  220uF  [TCAP_CASEE]
D1  MM5Z5V1S  [DIO_SOD-523_A1]
D2  CDBQR0130L  [DIO-0402]
D4  R  [LED-0603]
D5  G  [LED-0603]
F1  6A, 6V DC  [FUSE_1210_A1]
J1  CON_PWRJACK  [CON_PWR-JACK_2M_6_TH_RA_A_A1]
P1  ESD8472MUT5G  [DIO-0201]
Q1  SSM6J501NU  [UDFN-6L_0P65_2X2_EP]
Q2  MMBT2907A  [SOT23-3L_1P9_3P12X1P5]
Q3  2N7002L  [SOT23-3L_1P9_2P9X1P3]
R1  2.2K  [0402]
R3  100K  [0402]
R4  10K  [0402]
R5  4.7K  [0402]
R6  1K  [0402]
R7  1K  [0402]
R8  100K  [0402]
R9  100K  [0402]
SW1  OS102011MS2QN1  [SW3_2_8P6X4P3_TH_ST]
TP1  SMD  [TP40_SMD]
sheet P04_PMIC TPS6521815
C6  4.7uF  [0603]
C7  10uF  [0402]
C8  0.1uF  [0402]
C9  0.1uF  [0402]
C10  10uF  [0402]
C11  0.1uF  [0402]
C12  4.7uF  [0603]
C13  4.7uF  [0603]
C14  4.7uF  [0603]
C15  4.7uF  [0603]
C16  4.7uF  [0603]
C17  4.7uF  [0603]
C18  10uF  [0402]
C19  47uF  [0805_B_A1]
C20  0.1uF  [0402]
C21  10uF  [0402]
C22  0.1uF  [0402]
C23  22uF  [0603]
C24  22uF  [0603]
C26  10uF  [0402]
C27  4.7uF  [0603]
C28  4.7uF  [0603]
C29  0.1uF  [0402]
C30  22uF  [0603]
C31  22uF  [0603]
C32  4.7uF  [0603]
C33  1uF  [0402]
C34  0.1uF  [0402]
C600  4.7uF  [0603]
DA8  LTST-C195TBKFKT-2A  [LED4_0P85_1P5X1P6]
L1  1.5uH  [IND_0806_B_A1]
L2  1.5uH  [IND_0806_B_A1]
L3  1.5uH  [IND_0806_B_A1]
L4  1.5uH  [IND_0806_B_A1]
L5  10uH  [IND-0805_1P45]
L6  10uH  [IND-0805_1P45]
Q17  MMBT3904  [SOT23-3L_1P9_2P9X1P3]
Q41  MMBT3904  [SOT23-3L_1P9_2P9X1P3]
R10  100K  [0402]
R11  10E  [0402]
R12  0E  [0402]
R13  200E  [0402]
R14  300E  [0402]
R15  100K  [0402]
R16  1M  [0402]
R17  1M  [0402]
R18  100K  [0402]
R19  300K  [0402]
R20  100K  [0402]
R21  0E  [0402]
R22  100K  [0402]
R23  100K  [0402]
R24  29.4K  [0402]
R25  2.2K  [0402]
R26  100K  [0402]
R28  10K  [0402]
R763  200K  [0402]
R766  1K  [0402]
R768  0E  [0402]
R769  0E  [0402]
R780  10mE  [0603]
R781  1K  [0402]
R782  1K  [0402]
R802  0E  [0402]
R803  0E  [0402]
R842  0E  [0402]
R843  200K  [0402]
R859  0E  [0402]
SW2  B3U-3100PM-B  [SW3_1P7_3X2P5_SM_RA_A1]
TP34  SMD  [TP40_SMD]
TP35  SMD  [TP40_SMD]
TP36  SMD  [TP40_SMD]
TP37  SMD  [TP40_SMD]
TP38  SMD  [TP40_SMD]
TP39  SMD  [TP40_SMD]
TP40  SMD  [TP40_SMD]
TP44  SMD  [TP40_SMD]
TP45  SMD  [TP40_SMD]
TP46  SMD  [TP40_SMD]
TP47  SMD  [TP40_SMD]
U1  TPS6521815RSL  [VQFN48_0P4_6X6_EP_A1]
U2  SN74LV1T126DCK  [SC70-5L_0P65_2X1P25_B_A1]
sheet P05_SWITCHES_COIN CELL_WD
BH1  BK-912  [BAT3_21P97_21P08X15P24_A1]
C35  10uF  [0402]
C36  1uF  [0402]
C37  4.7uF  [0402]
C38  0.1uF  [0402]
C39  2.2uF  [0402]
C40  2.2uF  [0402]
C41  10uF  [0402]
C42  1uF  [0402]
C43  1uF  [0402]
C596  1uF  [0402]
R31  0E  [0402]
R32  0E  [0402]
R34  100K  [0402]
R35  100K  [0402]
R36  10K  [0402]
R37  100K  [0402]
R800  0E  [0402]
R801  0E  [0402]
R805  100K  [0402]
R806  100K  [0402]
R865  0E  [0402]
U3  TPS22964C  [BGA6_0P5_0P942X1P442_A1]
U4  FPF1321UCX  [WLCSP6_0P5_0P96X1P46_A1]
U5  TPS22964C  [BGA6_0P5_0P942X1P442_A1]
Z1  3V, 225mAh  [BAT_3_22P9X5P8_TH_NCP]
sheet P06_IMX POWER
C44  22uF  [0603]
C45  0.22uF  [0402]
C46  0.22uF  [0402]
C47  0.22uF  [0402]
C48  22uF  [0603]
C49  4.7uF  [0402]
C50  0.22uF  [0402]
C51  0.22uF  [0402]
C52  0.22uF  [0402]
C53  0.22uF  [0402]
C54  22uF  [0603]
C55  4.7uF  [0402]
C56  0.22uF  [0402]
C57  10uF  [0402]
C58  0.22uF  [0402]
C59  0.22uF  [0402]
C60  10uF  [0402]
C61  0.22uF  [0402]
C62  0.22uF  [0402]
D6  CDBQR0130L  [DIO-0402]
TP49  SMD  [TP40_SMD]
TP50  SMD  [TP40_SMD]
TP51  SMD  [TP40_SMD]
TP52  SMD  [TP40_SMD]
TP53  SMD  [TP40_SMD]
TP54  SMD  [TP40_SMD]
U6  MCIMX6Y2CVM08AB  [BGA289_0P8_14X14_A1]  (sections A,B,C,D,E,F,G,H,I,J,K)
sheet P07_IMX-DDR3L
C63  0.22uF  [0402]
C64  0.22uF  [0402]
C65  10uF  [0402]
C66  0.22uF  [0402]
C67  0.22uF  [0402]
C68  0.22uF  [0402]
C69  0.22uF  [0402]
C70  0.22uF  [0402]
C71  0.22uF  [0402]
C72  0.22uF  [0402]
C73  0.22uF  [0402]
C74  1uF  [0201]
C75  1uF  [0201]
C76  1uF  [0201]
C77  1uF  [0201]
C78  0.1uF  [0201]
C79  0.1uF  [0201]
C80  0.1uF  [0201]
C81  0.1uF  [0201]
C82  0.1uF  [0201]
C83  0.1uF  [0201]
C84  0.1uF  [0201]
C85  0.1uF  [0201]
C86  0.1uF  [0201]
C87  4.7uF  [0402]
C88  0.1uF  [0402]
R58  10K  [0402]
R60  10K  [0402]
R62  240E  [0402]
R63  240E  [0402]
R64  10K  [0402]
R65  240E  [0402]
R66  1.5K  [0402]
R67  100E  [0402]
R68  1.5K  [0402]
U7  MT41K256M16TW-107:P  [BGA96_0P8_8X14_A1]
sheet P08_IMX-LCD,ENET,eMMC,SDIO
C89  0.22uF  [0402]
C90  0.22uF  [0402]
C91  0.22uF  [0402]
C92  0.22uF  [0402]
C93  18pF  [0402]
R69  0E  [0402]
R70  0E  [0402]
R71  22E  [0402]
R72  10K  [0402]
R73  10K  [0402]
R74  10K  [0402]
R75  10K  [0402]
R76  10K  [0402]
R78  33E  [0402]
R79  33E  [0402]
R80  33E  [0402]
R81  22E  [0402]
R82  22E  [0402]
R83  33E  [0402]
R84  33E  [0402]
R85  33E  [0402]
R773  510E  [0402]
R779  510E  [0402]
R809  33E  [0402]
sheet P09_IMX - CSI,USB,ADC,GPIO
C94  10uF  [0402]
C95  10uF  [0402]
C96  0.22uF  [0402]
C97  10uF  [0402]
C98  0.1uF  [0402]
C99  0.22uF  [0402]
C100  10uF  [0402]
C101  0.1uF  [0402]
R33  0E  [0402]
R86  10K  [0402]
R770  10K  [0402]
R814  10K  [0402]
R815  10K  [0402]
TP33  SMD  [TP40_SMD]

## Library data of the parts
C1 C8 C9 C11 C20 C22 C29 C34 C38 C88 C98 C101 = CAP_NP: Cap, Cer-X7R, 0.1uF, 16V, 10%, 0402; EN: 102-1-01629; KEY Number: 102-1-01629@1; Mfg: WALSIN TECHNOLOGY CORP.; Mfg Part No: 0402B104K160CT; Temperature: -55°C to +125°C
C2 = CAP_NP: Cap, Cer-X7R, 0.01uF, 25V, 10%, 0402; EN: 102-1-00027; FPLIST: 0402,0402_CIR; KEY Number: 102-1-00027@3; Mfg: WALSIN TECHNOLOGY CORP.; Mfg Part No: 0402B103K250; Temperature: -55°C to +125°C
C3 = CAP_POL: Cap, Tant, 100uF, 16V, 10%, SizeD; EN: 102-2-00097; KEY Number: 102-2-00097@1; Mfg: AVX CORPORATION; Mfg Part No: TAJD107K016RNJ
C4 C23 C24 C30 C31 C44 C48 C54 = CAP_NP: Cap, Cer-X5R, 22uF, 10V, 20%, 0603; EN: 102-1-01791; KEY Number: 102-1-01791@2; Mfg: WALSIN TECHNOLOGY CORP.; Mfg Part No: 0603X226M100CT; Temperature: -55°C to +85°C
C5 C33 C36 C42 C43 C596 = CAP_NP: Cap, Cer-X5R, 1uF, 16V, 10%, 0402; EN: 102-1-01745; KEY Number: 102-1-01745@3; Mfg: AVX CORPORATION; Mfg Part No: 0402YD105KAT2A; Temperature: -55°C to +85°C
C590 = CAP_POL: Cap, Tant, 220uF, 16V, 10%, SizeE; EN: 102-2-00122; KEY Number: 102-2-00122@1; Mfg: AVX CORPORATION; Mfg Part No: TAJE227K016RNJ
D1 = DIODE_ZEN: Diode, Zener, 5.1V, 5mA, 0.5W, SOD-523; EN: 106-3-00149; KEY Number: 106-3-00149@1; Mfg: ON SEMICONDUCTOR; Mfg Part No: MM5Z5V1ST1G; Temperature: -65°C to +150°C
D2 D6 = DIODE_SCH: Diode, Schottky, 0.1A, 30V, 0.125W, 0402; EN: 106-2-00083; KEY Number: 106-2-00083@1; Mfg: COMCHIP TECHNOLOGY; Mfg Part No: CDBQR0130L-HF; Temperature: -40°C to +125°C
D4 = DIODE_LED: LED, Single, Red, 0603; EN: 106-4-00009; KEY Number: 106-4-00009@1; Mfg: LUMEX; Mfg Part No: SML-LX0603IW-TR; Temperature: -25°C to +85°C
D5 = DIODE_LED: LED, Single, Green, 0603; EN: 106-4-00005; KEY Number: 106-4-00005@1; Mfg: DIALIGHT; Mfg Part No: 598-8070-107F; Temperature: -30°C to +85°C
F1 = FUSE: Fuse, Resettable, 6A, 6V DC, PTC, SMD1210; EN: 305-1-00641; KEY Number: 305-1-00641@1; Mfg: LITTELFUSE; Mfg Part No: MICROSMD600LR-2; Temperature: -40°C to +80°C
J1 = CONN_PWRJACK_4P_A_A1: Conn, DC PWR Jack, 1x1, 8A, 2.5mm ID, 6.5mm OD,  RA, TH; EN: 201-2-01385; KEY Number: 201-2-01385@1; Mfg: CUI INC; Mfg Part No: PJ-063BH; Temperature: -25°C to +85°C
P1 = PROT_ZENX2_NET_2P_A: TVS-Zener Diode, Bi, 7V, AEC-Q101, X3DFN-2; EN: 305-1-00135; KEY Number: 305-1-00135@1; Mfg: ON SEMICONDUCTOR; Temperature: -55°C to +150°C
Q1 = TRANS_PMOSX1_8P: Transistor, P-MOSFET, 20V, 10A, Vgs=8V, 1W, UDFN-6B; EN: 107-2-00034; KEY Number: 107-2-00034@1; Mfg: TOSHIBA CORPORATION
Q2 = TRANS_PNP: Transistor, BJT, PNP, 60V, 0.8A, 0.35W, SOT23-3; EN: 107-1-00031; KEY Number: 107-1-00031@1; Mfg: FAIRCHILD - ON SEMICONDUCTOR; Temperature: -55°C to +155°C
Q3 = TRANS_NMOS-ENX1_3P: Transistor, N-MOSFET, 60V, 0.115A, Vgs=20V, 0.225W, SOT-23; EN: 107-2-00143; KEY Number: 107-2-00143@1; Mfg: ON SEMICONDUCTOR; Mfg Part No: 2N7002L**G; Temperature: -55°C to +150°C
R1 R25 = RES_v2: Res, Chip, 2.2K, 1/10W, 1%, AEC-Q200, 0402; EN: 101-1-03621; KEY Number: 101-1-03621@1; Mfg: KOA SPEER ELECTRONICS, INC.; Mfg Part No: RK73H1ETTP2201F; Temperature: -55°C to +155°C
R3 R8-R10 R15 R18 R20 R22 R23 R26 R34 R35 R37 R805 R806 = RES_v2: Res, Chip, 100K, 1/16W, 1%, 0402; EN: 101-1-00485; KEY Number: 101-1-00485@3; Mfg: WALSIN TECHNOLOGY CORP.; Mfg Part No: WR04X1003FTL; Temperature: -55°C to +155°C
R4 R28 R36 R58 R60 R64 R72-R76 R86 R770 R814 R815 = RES_v2: Res, Chip, 10K, 1/10W, 1%, AEC-Q200, 0402; EN: 101-1-00389; KEY Number: 101-1-00389@2; Mfg: PANASONIC; Mfg Part No: ERJ2RKF1002X; Temperature: -55°C to +155°C
R5 = RES_v2: Res, Chip, 4.7K, 1/16W, 1%, 0402; EN: 101-1-03446; KEY Number: 101-1-03446@2; Mfg: WALSIN TECHNOLOGY CORP.; Mfg Part No: WR04X4701FTL; Temperature: -55°C to +155°C
R6 R7 R766 R781 R782 = RES_v2: Res, Chip, 1K, 1/16W, 5%, 0402; EN: 101-1-02769; KEY Number: 101-1-02769@4; Mfg: WALSIN TECHNOLOGY CORP.; Mfg Part No: WR04X102JTL; Temperature: -55°C to +155°C
SW1 = SWITCH_SPDT_5P: Switch, Slide, SPDT, 12V, Vertical, TH; EN: 205-1-00079; KEY Number: 205-1-00079@1; Mfg: C&K COMPONENTS; Temperature: -30°C to +70°C
TP1 TP33-TP40 TP44-TP47 TP49-TP54 = TEST_POINT_SMD: Testpoint, Pad=1mm, SM=1.3mm, SMD; EN: 666-1-00008; KEY Number: 666-1-00008@1; Mfg: NA; Mfg Part No: 666-1-00008
C6 C12-C17 C27 C28 C32 C600 = CAP_NP: Cap, Cer-X5R, 4.7uF, 16V, 10%, 0603; EN: 102-1-00091; KEY Number: 102-1-00091@4; Mfg: MURATA MANUFACTURING CO,LTD; Mfg Part No: GRM188R61C475KAAJD; Temperature: -55°C to +85°C
C7 C10 C18 C21 C26 C35 C41 C57 C60 C65 C94 C95 C97 C100 = CAP_NP: Cap, Cer-X5R, 10uF, 10V,  20%, 0402; EN: 102-1-01803; KEY Number: 102-1-01803@6; Mfg: MURATA MANUFACTURING CO,LTD; Mfg Part No: GRM155R61A106ME11D; Temperature: -55°C to +85°C
C19 = CAP_NP: Cap, Cer-X5R, 47uF, 10V, 20%, 0805; EN: 102-1-02136; KEY Number: 102-1-02136@1; Mfg: MURATA MANUFACTURING CO,LTD; Mfg Part No: GRM21BR61A476ME15L; Temperature: -55°C to +85°C
DA8 = DIODE_NETX2_LED-BO_4P: LED, Single, (Blue/Orange), SMD; EN: 106-4-00160; KEY Number: 106-4-00160@1; Mfg: LITE-ON; Temperature: -20°C to +80°C
L1-L4 = IND_CORE_A: Ind, Power, 1.5uH, 20%, 1.8A, 110mE, Shielded, SMD0806; EN: 103-1-00424; KEY Number: 103-1-00424@2; Mfg: MURATA MANUFACTURING CO,LTD; Mfg Part No: DFE201610P-1R5M; Temperature: -40°C to +125°C
L5 L6 = IND_CORE_B: Ind, Power, 10uH, +/-20%, 0.5A, 0.39E, Shielded, SMD0805; EN: 103-1-00216; KEY Number: 103-1-00216@1; Mfg: TDK CORPORATION; Mfg Part No: MLZ2012N100LT***; Temperature: -55°C to +125°C
Q17 Q41 = TRANS_NPN: Transistor, BJT, NPN, 40V, 0.2A, SOT23-3; EN: 107-1-00001; KEY Number: 107-1-00001@1; Mfg: FAIRCHILD - ON SEMICONDUCTOR; Temperature: -55°C to +150°C
R11 = RES_v2: Res, Chip, 10E, 1/16W, 1%, AEC-Q200, 0402; EN: 101-1-00101; KEY Number: 101-1-00101@2; Mfg: VISHAY; Mfg Part No: CRCW040210R0FKED; Temperature: -55°C to +155°C
R12 R21 R31-R33 R69 R70 R768 R769 R800-R803 R842 R859 R865 = RES_v2: Res, Chip, 0E, 1/16W, 1.5A, AEC-Q200, 0402; EN: 101-1-00001; KEY Number: 101-1-00001@2; Mfg: VISHAY; Mfg Part No: CRCW04020000Z0ED; Temperature: -55°C to +155°C
R13 = RES_v2: Res, Chip, 200E, 1/10W, 1%, AEC-Q200, 0402; EN: 101-1-00226; KEY Number: 101-1-00226@2; Mfg: PANASONIC; Mfg Part No: ERJ2RKF2000X; Temperature: -55°C to +155°C
R14 = RES_v2: Res, Chip, 300E, 1/16W, 5%, 0402; EN: 101-1-02756; KEY Number: 101-1-02756@2; Mfg: VISHAY; Mfg Part No: CRCW0402300RJNED; Temperature: -55°C to +155°C
R16 R17 = RES_v2: Res, Chip, 1M, 1/10W, 1%, AEC-Q200, 0402; EN: 101-1-00581; KEY Number: 101-1-00581@1; Mfg: KOA SPEER ELECTRONICS, INC.; Mfg Part No: RK73H1ETTP1004F; Temperature: -55°C to +155°C
R19 = RES_v2: Res, Chip, 300K, 1/16W, 1%, 0402; EN: 101-1-03396; KEY Number: 101-1-03396@1; Mfg: VISHAY; Mfg Part No: CRCW0402300KFK**; Temperature: -55°C to +155°C
R24 = RES_v2: Res, Chip, 29.4K, 1/16W, 1%, 0402; EN: 101-1-00434; KEY Number: 101-1-00434@2; Mfg: VISHAY; Mfg Part No: CRCW040229K4FK; Temperature: -55°C to +155°C
R763 R843 = RES_v2: Res, Chip, 200K, 1/16W, 1%, 0402; EN: 101-1-00514; KEY Number: 101-1-00514@3; Mfg: WALSIN TECHNOLOGY CORP.; Mfg Part No: WR04X2003FTL; Temperature: -55°C to +155°C
R780 = RES_v2: Res, I-Sense, 10mE, 1/4W, 1%, 0603; EN: 101-3-00046; KEY Number: 101-3-00046@2; Mfg: WALSIN TECHNOLOGY CORP.; Mfg Part No: WW06CR010FTL; Temperature: -55°C to +125°C
SW2 = SWITCH_PUSH-2_3P_A: Switch, Tactile, SPST-NO, 12V, 50mA, with Boss, RA, SMD; EN: 205-1-00128; KEY Number: 205-1-00128@1; Mfg: OMRON CORP.; Temperature: -25°C to +70°C
U1 = IC_TPS65218D0_QFN-48P_EP_CST_A2: IC, TPS6521815, PMIC, 7 Outputs, 6-DC/DCs&1-LDOs, (Non-Programmed version), VQFN-48; EN: 301-4-01247; KEY Number: 301-4-01247@1; Mfg: TEXAS INSTRUMENTS; Mfg Part No: TPS6521815RSLT; Temperature: -40°C to +105°C
U2 = IC_GATE_BUFX1_5P_H_A1: IC, SN74LV1T126, Single Buffer, 3-State O/P, CMOS Logic Level Shifter, SC70-5; EN: 301-0-02907; KEY Number: 301-0-02907@1; Mfg: TEXAS INSTRUMENTS; Mfg Part No: SN74LV1T126DCKR; Temperature: -40°C to +125°C
BH1 = BATT_HOLDER_3P_B: Battery Holder, BK-912, Coin-20mm, SMD; EN: 401-1-01218; KEY Number: 401-1-01218@1; Mfg: MEMORY PROTECTION DEVICE; Temperature: -40°C to +260°C
C37 C49 C55 C87 = CAP_NP: Cap, Cer-X5R, 4.7uF, 10V, 10%, 0402; EN: 102-1-02063; KEY Number: 102-1-02063@1; Mfg: TDK CORPORATION; Mfg Part No: C1005X5R1A475K050BC; Temperature: -55°C to +85°C
C39 C40 = CAP_NP: Cap, Cer-X5R, 2.2uF, 10V, 10%, 0402; EN: 102-1-00208; FPLIST: 0402,0402_HD; KEY Number: 102-1-00208@4; Mfg: MURATA MANUFACTURING CO,LTD; Mfg Part No: GRM155R61A225KE95; Temperature: -55°C to +85°C
U3 U5 = IC_LOAD_SWITCH_6P_F_A1: IC, Load switch, 1-5.5Vin, 3A, DSBGA-6; EN: 301-0-01503; KEY Number: 301-0-01503@1; Mfg: TEXAS INSTRUMENTS; Mfg Part No: TPS22964CYZP*; Temperature: -40°C to +85°C
U4 = IC_LOAD_SWITCH_6P_N_A1: IC, Load Switch, 1.5-5.5Vin, 1.5A, DISO Channel, WLCSP-6; EN: 301-0-02703; KEY Number: 301-0-02703@1; Mfg: ON SEMICONDUCTOR; Temperature: -40°C to +85°C
Z1 = BATT_CELL_NON_CAD: Battery, Coin-Cell, Li-ion, 3V, 225mAh, 20mm, 2032, Holder Mount; EN: 204-1-00002; KEY Number: 204-1-00002@1; Mfg: PANASONIC; Mfg Part No: CR2032; Temperature: -30°C to +60°C
C45-C47 C50-C53 C56 C58 C59 C61-C64 C66-C73 C89-C92 C96 C99 = CAP_NP: Cap, Cer-X5R, 0.22uF, 10V, 10%, 0402; EN: 102-1-00210; FPLIST: 0402,0402_CIR; KEY Number: 102-1-00210@1; Mfg: MURATA MANUFACTURING CO,LTD; Mfg Part No: GRM155R61A224KE19D; Temperature: -55°C to +85°C
U6 = IC_IMX6ULL_BGA-289P_CST_A1: IC, uP, iMX6ULL, ARM Cortex-A7 Application Processor, 792MHz, MAPBGA-289; EN: 301-1-00454; KEY Number: 301-1-00454@1; Mfg: NXP SEMICONDUCTORS; Temperature: -40°C to +105°C
C74-C77 = CAP_NP: Cap, Cer-X5R, 1uF, 10V, 10%, 0201; EN: 102-1-02132; KEY Number: 102-1-02132@1; Mfg: SAMSUNG ELECTRO-MECHANICS AMERICA, INC; Mfg Part No: CL03A105KP3NSNC; Temperature: -55°C to +85°C
C78-C86 = CAP_NP: Cap, Cer-X5R, 0.1uF, 10V, 10%, 0201; EN: 102-1-01653; FPLIST: 0201,CAP_0201_HD; KEY Number: 102-1-01653@2; Mfg: WALSIN TECHNOLOGY CORP.; Mfg Part No: 0201X104K100CT; Temperature: -55°C to +85°C
R62 R63 R65 = RES_v2: Res, Chip, 240E, 1/16W, 1%, 0402; EN: 101-1-03473; KEY Number: 101-1-03473@1; Mfg: YAGEO; Mfg Part No: RC0402FR-07240RL; Temperature: -55°C to +155°C
R66 R68 = RES_v2: Res, Chip, 1.5K, 1/16W, 1%, 0402; EN: 101-1-00310; KEY Number: 101-1-00310@3; Mfg: WALSIN TECHNOLOGY CORP.; Mfg Part No: WR04X1501FTL; Temperature: -55°C to +155°C
R67 = RES_v2: Res, Chip, 100E, 1/16W, 1%, 0402; EN: 101-1-00197; KEY Number: 101-1-00197@3; Mfg: WALSIN TECHNOLOGY CORP.; Mfg Part No: WR04X1000FTL; Temperature: -55°C to +155°C
U7 = IC_DDR3-SDRAMX16_BGA-96P_D: IC, DDR3L SDRAM, 512MB, x16bit, 800MHz, FBGA-96; EN: 301-2-00639; KEY Number: 301-2-00639@1; Mfg: MICRON; Temperature: 0°C to +95°C
C93 = CAP_NP: Cap, Cer-NPO, 18pF, 50V, 5%, 0402; EN: 102-1-01806; KEY Number: 102-1-01806@2; Mfg: WALSIN TECHNOLOGY CORP.; Mfg Part No: 0402N180J500CT; Temperature: -55°C to +125°C
R71 R81 R82 = RES_v2: Res, Chip, 22E, 1/10W, 1%, AEC-Q200, 0402; EN: 101-1-03406; KEY Number: 101-1-03406@3; Mfg: PANASONIC; Mfg Part No: ERJ2RKF22R0X; Temperature: -55°C to +155°C
R78-R80 R83-R85 R809 = RES_v2: Res, Chip, 33E, 1/16W, 1%, 0402; EN: 101-1-03680; KEY Number: 101-1-03680@2; Mfg: WALSIN TECHNOLOGY CORP.; Mfg Part No: WR04X33R0FTL; Temperature: -55°C to +155°C
R773 R779 = RES_v2: Res, Chip, 510E, 1/16W, 1%, 0402; EN: 101-1-03412; KEY Number: 101-1-03412@2; Mfg: WALSIN TECHNOLOGY CORP.; Mfg Part No: WR04X5100FTL; Temperature: -55°C to +155°C

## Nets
5VIN: C1.1 C2.1 F1.2 Q1.4(SOURCE1) Q1.8(SOURCE2) Q2.2(EMITTER) R1.2 R3.2 R6.1
GND: BH1.2(NEG) C1.2 C3.2(CATHODE) C4.2 C5.2 C6.2 C7.2 C8.2 C9.2 C10.2 C11.2 C12.2 C13.2 C14.2 C15.2 C16.2 C17.2 C18.2 C19.2 C20.2 C21.2 C22.2 C23.2 C24.2 C26.2 C27.2 C28.2 C29.2 C30.2 C31.2 C32.2 C33.2 C34.2 C35.2 C36.2 C37.2 C38.2 C39.2 C40.2 C41.2 C42.2 C43.2 C44.2 C45.2 C46.2 C47.2 C48.2 C49.2 C50.2 C51.2 C52.2 C53.2 C54.2 C55.2 C56.2 C57.2 C58.2 C59.2 C60.2 C61.2 C62.2 C63.2 C64.2 C65.2 C66.2 C67.2 C68.2 C69.2 C70.2 C71.2 C72.2 C73.2 C74.2 C75.2 C76.2 C77.2 C78.2 C79.2 C80.2 C81.2 C82.2 C83.2 C84.2 C85.2 C86.2 C87.2 C88.2 C89.2 C90.2 C91.2 C92.2 C93.2 C94.2 C95.2 C96.2 C97.2 C98.2 C99.2 C100.2 C101.2 C590.2(CATHODE) C596.2 C600.2 D1.2(A) D5.1(K) DA8.4(OK) J1.2 J1.S1 J1.S2 P1.1 Q3.2(SOURCE) Q17.2(EMITTER) Q41.2(EMITTER) R9.1 R14.2 R15.1 R16.2 R17.1 R19.2 R21.2 R24.1 R37.2 R58.2 R60.2 R62.2 R63.1 R64.1 R65.2 R68.1 R770.1 R773.1 R779.1 R805.2 R806.2 R815.1 R843.1 SW1.2(COM) SW1.3 SW1.S1 SW1.S2 SW2.1 SW2.3 TP51.1 U1.49(GND_EP) U2.3(GND) U3.C1(GND) U4.C1(GND) U5.C1(GND) U6.A1(VSS1) U6.A17(VSS2) U6.C3(VSS3) U6.C7(VSS4) U6.C11(VSS5) U6.C15(VSS6) U6.E8(VSS7) U6.E11(VSS8) U6.F6(VSS9) U6.F7(VSS10) U6.F8(VSS11) U6.F9(VSS12) U6.F10(VSS13) U6.F11(VSS14) U6.F12(VSS15) U6.G3(VSS16) U6.G5(VSS17) U6.G7(VSS18) U6.G12(VSS19) U6.G15(VSS20) U6.H7(VSS21) U6.H12(VSS22) U6.J5(VSS23) U6.J7(VSS24) U6.J12(VSS25) U6.K7(VSS26) U6.K12(VSS27) U6.L3(VSS28) U6.L7(VSS29) U6.L12(VSS30) U6.M7(VSS31) U6.M8(VSS32) U6.M9(VSS33) U6.M10(VSS34) U6.M11(VSS35) U6.M12(NGND_KEL0) U6.N3(VSS36) U6.N5(VSS37) U6.R3(VSS38) U6.R5(VSS39) U6.R7(VSS40) U6.R11(VSS41) U6.R16(VSS42) U6.R17(VSS43) U6.T14(VSS44) U6.U1(VSS45) U6.U14(VSS46) U6.U17(VSS47) U7.A9(VSS1) U7.B1(VSSQ1) U7.B3(VSS2) U7.B9(VSSQ2) U7.D1(VSSQ3) U7.D8(VSSQ4) U7.E1(VSS3) U7.E2(VSSQ5) U7.E8(VSSQ6) U7.F9(VSSQ7) U7.G1(VSSQ8) U7.G8(VSS4) U7.G9(VSSQ9) U7.J2(VSS5) U7.J8(VSS6) U7.M1(VSS7) U7.M9(VSS8) U7.P1(VSS9) U7.P9(VSS10) U7.T1(VSS11) U7.T9(VSS12) ; also on sheet 10 11 12 13 14 15 16 17 18 19 20 21
VDD_1V0: C30.1 L5.2 TP37.1 U1.21(FB5)
VDD_1V8: C39.1 C90.1 R69.1 U4.C2(VINB) U6.E7(NVCC_NAND) ; also on sheet 11 12 18 19 20
VDD_1V8_SNS: C19.1 C20.1 TP47.1 U1.15(DCDC4) ; also on sheet 18
VDD_ARM_CAP: C46.1 C47.1 C48.1 TP49.1 U6.G9(VDD_ARM_CAP1) U6.G10(VDD_ARM_CAP2) U6.G11(VDD_ARM_CAP3) U6.H11(VDD_ARM_CAP4)
VDD_COINCELL_IN: BH1.1(POS1) BH1.3(POS2) C37.1 R11.2 R32.1
VDD_DCDC6: C31.1 L6.2 R13.2 R802.2
VDD_DCJACK_5VIN: F1.1 J1.1
VDD_EXT_LS_5V0: R800.1 R801.1 R865.1 ; also on sheet 16 18
VDD_EXT_LS_5V0_SNS: C43.1 U5.A1(VOUT1) U5.B1(VOUT2) ; also on sheet 18
VDD_HIGH_CAP: C57.1 C58.1 C72.1 TP52.1 U6.N6(NVCC_DRAM_2P5) U6.R14(VDD_HIGH_CAP1) U6.R15(VDD_HIGH_CAP2)
VDD_HIGH_IN_3V3: C27.1 C28.1 C35.1 C36.1 C40.1 C55.1 C56.1 D6.2(A) R28.2 R34.2 R35.2 U1.5(IN_LDO1) U1.31(IN_LS1) U1.39(FB3) U3.A2(VIN1) U3.B2(VIN2) U4.A2(VINA) U6.N13(VDD_HIGH_IN) ; also on sheet 18
VDD_HIGH_IN_3V3_SNS: C10.1 C11.1 L3.2 TP46.1 ; also on sheet 18
VDD_IN_BU: C600.1 R12.1 U1.27(IN_BU)
VDD_LDO1: C21.1 C22.1 R780.2 U1.4(LDO1)
VDD_LDO_2V8: R780.1 TP38.1 ; also on sheet 19
VDD_NVCC_3V3: C26.1 C29.1 C91.1 C96.1 C99.1 C100.1 C101.1 R16.1 R25.2 R70.1 R86.1 R814.1 TP39.1 U1.30(LS1) U2.1(OE) U6.F4(NVCC_CSI) U6.F13(NVCC_ENET) U6.J13(NVCC_GPIO) U6.L13(VDDA_ADC_3P3) U6.M13(ADC_VREFH) ; also on sheet 10 16 20
VDD_NVCC_SD1: C42.1 C92.1 R72.1 R73.1 R74.1 R75.1 R76.1 U4.B2(VOUT) U6.C4(NVCC_SD1)
VDD_PERI_3V3: C38.1 U3.A1(VOUT1) U3.B1(VOUT2) ; also on sheet 11 12 13 14 16 17 18 19 20
VDD_PMIC_LS_5V0: C94.1 C95.1 R36.1 R800.2 R801.2 R865.2 U6.T12(USB_OTG1_VBUS) U6.U12(USB_OTG2_VBUS) ; also on sheet 16 18
VDD_PMIC_LS_5V0_SNS: C23.1 C24.1 U1.7(LS3) U1.33(LS2) ; also on sheet 18
VDD_SNVS_CAP: C62.1 TP54.1 U6.N12(VDD_SNVS_CAP)
VDD_SNVS_IN: C61.1 D6.1(K) R18.2 R23.1 R26.1 R32.2 R763.2 R802.1 TP36.1 U2.5(VCC) U6.P12(VDD_SNVS_IN) ; also on sheet 10 20
VDD_SOC_ARM_IN: C44.1 C45.1 C49.1 C50.1 U1.47(FB1) U6.H9(VDD_SOC_IN1) U6.H10(VDD_SOC_IN2) U6.J9(VDD_SOC_IN3) U6.J10(VDD_SOC_IN4) U6.K9(VDD_SOC_IN5) U6.K10(VDD_SOC_IN6) ; also on sheet 18
VDD_SOC_ARM_IN_SNS: C7.1 C8.1 L1.2 TP44.1 ; also on sheet 18
VDD_SOC_CAP: C51.1 C52.1 C53.1 C54.1 TP50.1 U6.G8(VDD_SOC_CAP1) U6.H8(VDD_SOC_CAP2) U6.J8(VDD_SOC_CAP3) U6.J11(VDD_SOC_CAP4) U6.K8(VDD_SOC_CAP5) U6.K11(VDD_SOC_CAP6) U6.L8(VDD_SOC_CAP7) U6.L9(VDD_SOC_CAP8) U6.L10(VDD_SOC_CAP9) U6.L11(VDD_SOC_CAP10)
VIN_PMIC_5V0: C3.1(ANODE) C4.1 C5.1 C6.1 C12.1 C13.1 C14.1 C15.1 C16.1 C17.1 C41.1 C590.1(ANODE) C596.1 DA8.1(BA) P1.2 Q1.1(DRAIN1) Q1.2(DRAIN2) Q1.5(DRAIN3) Q1.6(DRAIN4) Q1.7(DRAIN5) R7.2 R10.2 R12.2 R20.2 R22.2 R781.1 TP1.1 U1.1(IN_DCDC1) U1.6(IN_LS3) U1.12(IN_DCDC4) U1.32(IN_LS2) U1.36(IN_BIAS) U1.37(IN_DCDC3) U1.43(IN_DCDC2) U5.A2(VIN1) U5.B2(VIN2) ; also on sheet 20
BASE_CC#: Q17.1(BASE) R766.2
COLL_CC#: DA8.2(OA) Q17.3(COLLECTOR) R781.2 R782.1
DC34_SEL: R21.1 U1.17(DC34_SEL)
DC_SW: R5.1 SW1.1
DC_SW_CTL: C2.2 D2.1(K) Q1.3(GATE) R3.1 R5.2
DCDC1_L1: L1.1 U1.48(L1)
DCDC2_L2: L2.1 U1.42(L2)
DCDC3_L3: L3.1 U1.38(L3)
DCDC4_L4A: L4.1 U1.13(L4A)
DCDC4_L4B: L4.2 U1.14(L4B)
DCDC5_L5: L5.1 U1.20(L5)
DCDC6_L6: L6.1 U1.23(L6)
DDR_ZQPAD: R63.2 U7.L8(ZQ)
DEBUG_UART_RESET#: U6.E5(CSI_PIXCLK) ; also on sheet 17
DRAM_ADDR0: U6.L5(DRAM_ADDR00) U7.N3(A0)
DRAM_ADDR1: U6.H2(DRAM_ADDR01) U7.P7(A1)
DRAM_ADDR2: U6.K1(DRAM_ADDR02) U7.P3(A2)
DRAM_ADDR3: U6.M2(DRAM_ADDR03) U7.N2(A3)
DRAM_ADDR4: U6.K4(DRAM_ADDR04) U7.P8(A4)
DRAM_ADDR5: U6.L1(DRAM_ADDR05) U7.P2(A5)
DRAM_ADDR6: U6.G2(DRAM_ADDR06) U7.R8(A6)
DRAM_ADDR7: U6.H4(DRAM_ADDR07) U7.R2(A7)
DRAM_ADDR8: U6.J4(DRAM_ADDR08) U7.T8(A8)
DRAM_ADDR9: U6.L2(DRAM_ADDR09) U7.R3(A9)
DRAM_ADDR10: U6.M4(DRAM_ADDR10) U7.L7(A10/AP)
DRAM_ADDR11: U6.K3(DRAM_ADDR11) U7.R7(A11)
DRAM_ADDR12: U6.L4(DRAM_ADDR12) U7.N7(A12/BC#)
DRAM_ADDR13: U6.H3(DRAM_ADDR13) U7.T3(A13)
DRAM_ADDR14: U6.G1(DRAM_ADDR14) U7.T7(A14)
DRAM_ADDR15: U6.K5(DRAM_ADDR15) U7.M7(NC)
DRAM_CAS#: U6.J2(DRAM_CAS#) U7.K3(CAS#)
DRAM_CS0#: U6.N2(DRAM_CS0#) U7.L2(CS#)
DRAM_CS1#: U6.H5(DRAM_CS1#) U7.L1(NC)
DRAM_DATA0: U6.T4(DRAM_DATA00) U7.E3(DQ0)
DRAM_DATA1: U6.U6(DRAM_DATA01) U7.F7(DQ1)
DRAM_DATA2: U6.T6(DRAM_DATA02) U7.F2(DQ2)
DRAM_DATA3: U6.U7(DRAM_DATA03) U7.F8(DQ3)
DRAM_DATA4: U6.U8(DRAM_DATA04) U7.H3(DQ4)
DRAM_DATA5: U6.T8(DRAM_DATA05) U7.H8(DQ5)
DRAM_DATA6: U6.T5(DRAM_DATA06) U7.G2(DQ6)
DRAM_DATA7: U6.U4(DRAM_DATA07) U7.H7(DQ7)
DRAM_DATA8: U6.U2(DRAM_DATA08) U7.D7(DQ8)
DRAM_DATA9: U6.U3(DRAM_DATA09) U7.C3(DQ9)
DRAM_DATA10: U6.U5(DRAM_DATA10) U7.C8(DQ10)
DRAM_DATA11: U6.R4(DRAM_DATA11) U7.C2(DQ11)
DRAM_DATA12: U6.P5(DRAM_DATA12) U7.A7(DQ12)
DRAM_DATA13: U6.P3(DRAM_DATA13) U7.A2(DQ13)
DRAM_DATA14: U6.R2(DRAM_DATA14) U7.B8(DQ14)
DRAM_DATA15: U6.R1(DRAM_DATA15) U7.A3(DQ15)
DRAM_DQM0: U6.T7(DRAM_DQM0) U7.E7(LDM)
DRAM_DQM1: U6.T3(DRAM_DQM1) U7.D3(UDM)
DRAM_ODT0: U6.N1(DRAM_ODT0) U7.K1(ODT)
DRAM_ODT1: U6.F1(DRAM_ODT1) U7.J1(NC)
DRAM_RAS#: U6.M5(DRAM_RAS#) U7.J3(RAS#)
DRAM_RESET#: R64.2 U6.G4(DRAM_RESET) U7.T2(RESET#)
DRAM_SDBA0: U6.M1(DRAM_SDBA0) U7.M2(BA0)
DRAM_SDBA1: U6.H1(DRAM_SDBA1) U7.N8(BA1)
DRAM_SDBA2: U6.K2(DRAM_SDBA2) U7.M3(BA2)
DRAM_SDCKE0: R60.1 U6.M3(DRAM_SDCKE0) U7.K9(CKE)
DRAM_SDCKE1: R58.1 U6.J3(DRAM_SDCKE1) U7.J9(NC)
DRAM_SDCLK0_N: R67.1 U6.P2(DRAM_SDCLK0_N) U7.K7(CK#)
DRAM_SDCLK0_P: R67.2 U6.P1(DRAM_SDCLK0_P) U7.J7(CK)
DRAM_SDQS0_N: U6.P7(DRAM_SDQS0_N) U7.G3(LDQS#)
DRAM_SDQS0_P: U6.P6(DRAM_SDQS0_P) U7.F3(LDQS)
DRAM_SDQS1_N: U6.T2(DRAM_SDQS1_N) U7.B7(UDQS#)
DRAM_SDQS1_P: U6.T1(DRAM_SDQS1_P) U7.C7(UDQS)
DRAM_SDWE#: U6.J1(DRAM_SDWE#) U7.L3(WE#)
DRAM_VREF: C63.1 C64.1 C73.1 C88.1 R66.1 R68.2 U6.P4(DRAM_VREF) U7.H1(VREFDQ) U7.M8(VREFCA)
DRAM_ZQPAD: R65.1 U6.N4(DRAM_ZQPAD)
ENET1_TXD0: R78.2 U6.E15(ENET1_TX_DATA0)
ENET1_TXD1: R79.2 U6.E14(ENET1_TX_DATA1)
ENET1_TXEN: R80.2 U6.F15(ENET1_TX_EN)
ENET2_TXD0: R83.2 U6.A15(ENET2_TX_DATA0)
ENET2_TXD1: R84.2 U6.A16(ENET2_TX_DATA1)
ENET2_TXEN: R85.2 U6.B15(ENET2_TX_EN)
ENET_REF_CLK: R773.2 R779.2 U6.D17(ENET2_TX_CLK) U6.F14(ENET1_TX_CLK) ; also on sheet 13
ENETPHY_RESET#: U6.L17(GPIO1_IO03) ; also on sheet 13
FB_DCDC6: R13.1 R14.1 U1.22(FB6)
GPIO3_IO03: U6.C9(LCD_VSYNC) ; also on sheet 20
HUB_RESET#: U6.N17(GPIO1_IO08) ; also on sheet 14
INT_LDO: C34.1 U1.35(INT_LDO)
LCD_DATA0: U6.B9(LCD_DATA00) ; also on sheet 19 20
LCD_DATA1: U6.A9(LCD_DATA01) ; also on sheet 19 20
LCD_DATA2: U6.E10(LCD_DATA02) ; also on sheet 19 20
LCD_DATA3: U6.D10(LCD_DATA03) ; also on sheet 19 20
LCD_DATA4: U6.C10(LCD_DATA04) ; also on sheet 19 20
LCD_DATA5: U6.B10(LCD_DATA05) ; also on sheet 19 20
LCD_DATA6: U6.A10(LCD_DATA06) ; also on sheet 19 20
LCD_DATA7: U6.D11(LCD_DATA07) ; also on sheet 19 20
LCD_DATA8: U6.B11(LCD_DATA08) ; also on sheet 19 20
LCD_DATA9: U6.A11(LCD_DATA09) ; also on sheet 19 20
LCD_DATA10: U6.E12(LCD_DATA10) ; also on sheet 19 20
LCD_DATA11: U6.D12(LCD_DATA11) ; also on sheet 19 20
LCD_DATA12: U6.C12(LCD_DATA12) ; also on sheet 19 20
LCD_DATA13: U6.B12(LCD_DATA13) ; also on sheet 19 20
LCD_DATA14: U6.A12(LCD_DATA14) ; also on sheet 19 20
LCD_DATA15: U6.D13(LCD_DATA15) ; also on sheet 19 20
LCD_DATA16: U6.C13(LCD_DATA16) ; also on sheet 20
LCD_DATA17: U6.B13(LCD_DATA17) ; also on sheet 20
LCD_DATA18: U6.A13(LCD_DATA18) ; also on sheet 20
LCD_DATA19: U6.D14(LCD_DATA19) ; also on sheet 20
LCD_DATA20: U6.C14(LCD_DATA20) ; also on sheet 20
LCD_DATA21: U6.B14(LCD_DATA21) ; also on sheet 20
LCD_DATA22: U6.A14(LCD_DATA22) ; also on sheet 20
LCD_DATA23: U6.B16(LCD_DATA23) ; also on sheet 20
LCD_DATA/COMND: U6.D9(LCD_HSYNC) ; also on sheet 19
LCD_RD_E#: U6.B8(LCD_ENABLE) ; also on sheet 19
LCD_RESET#: U6.E9(LCD_RESET) ; also on sheet 19
LCD_WR_E#: U6.A8(LCD_CLK) ; also on sheet 19
NVCC_DRAM_1V35: C65.1 C66.1 C67.1 C68.1 C69.1 C70.1 C71.1 C74.1 C75.1 C76.1 C77.1 C78.1 C79.1 C80.1 C81.1 C82.1 C83.1 C84.1 C85.1 C86.1 C87.1 R66.2 U1.41(FB2) U6.G6(NVCC_DRAM1) U6.H6(NVCC_DRAM2) U6.J6(NVCC_DRAM3) U6.K6(NVCC_DRAM4) U6.L6(NVCC_DRAM5) U6.M6(NVCC_DRAM6) U7.A1(VDDQ1) U7.A8(VDDQ2) U7.B2(VDD1) U7.C1(VDDQ3) U7.C9(VDDQ4) U7.D2(VDDQ5) U7.D9(VDD2) U7.E9(VDDQ6) U7.F1(VDDQ7) U7.G7(VDD3) U7.H2(VDDQ8) U7.H9(VDDQ9) U7.K2(VDD4) U7.K8(VDD5) U7.N1(VDD6) U7.N9(VDD7) U7.R1(VDD8) U7.R9(VDD9) ; also on sheet 18
NVCC_DRAM_1V35_SNS: C9.1 C18.1 L2.2 TP45.1 ; also on sheet 18
NVCC_LCD: C89.1 R69.2 R70.2 U6.E13(NVCC_LCD) ; also on sheet 20
NVCC_PLL: C59.1 C60.1 TP53.1 U6.P13(NVCC_PLL)
ON_LS4: R36.2 R806.1 U5.C2(ON)
ON_LS5: R31.1 R805.1 U3.C2(ON)
OVRPRTC: Q3.1(GATE) R8.1 R9.2
OVRPRTC_LED: D4.1(K) Q3.3(DRAIN)
OVRPRTC_LED_PWR: D4.2(A) R6.2
PGOOD: R769.2 U1.8(PGOOD)
PGOOD_BU: R768.2 U1.19(PGOOD_BU)
PHY_MDC: U6.L16(GPIO1_IO07) ; also on sheet 13
PHY_MDIO: U6.K17(GPIO1_IO06) ; also on sheet 13
PHYA_CRSDV: U6.E16(ENET1_RX_EN) ; also on sheet 13
PHYA_RXD0: U6.F16(ENET1_RX_DATA0) ; also on sheet 13
PHYA_RXD1: U6.E17(ENET1_RX_DATA1) ; also on sheet 13
PHYA_RXER: U6.D15(ENET1_RX_ER) ; also on sheet 13
PHYA_TX_EN: R80.1 ; also on sheet 13
PHYA_TXD0: R78.1 ; also on sheet 13
PHYA_TXD1: R79.1 ; also on sheet 13
PHYB_CRSDV: U6.B17(ENET2_RX_EN) ; also on sheet 13
PHYB_RXD0: U6.C17(ENET2_RX_DATA0) ; also on sheet 13
PHYB_RXD1: U6.C16(ENET2_RX_DATA1) ; also on sheet 13
PHYB_RXER: U6.D16(ENET2_RX_ER) ; also on sheet 13
PHYB_TX_EN: R85.1 ; also on sheet 13
PHYB_TXD0: R83.1 ; also on sheet 13
PHYB_TXD1: R84.1 ; also on sheet 13
PMIC_AC_DET: R10.1 R15.2 U1.9(AC_DET)
PMIC_CC: C32.1 R11.1 U1.25(CC)
PMIC_GPIO1: R28.1 R31.2 U1.11(GPIO1)
PMIC_I2C1_SCL: U1.3(SCL) ; also on sheet 10 17
PMIC_I2C1_SDA: U1.2(SDA) ; also on sheet 10 17
PMIC_IN_CC#: R766.1 U1.18(IN_CC#)
PMIC_INT#: R25.1 U1.45(INT#) U6.F5(CSI_MCLK)
PMIC_PB: R842.1 ; also on sheet 10
PMIC_PB_B: R20.1 R842.2 R843.2 SW2.2 U1.44(PB#)
PMIC_PFI: R22.1 R24.2 U1.16(PFI)
PMIC_PFO#: R859.2 U1.10(PFO#) ; also on sheet 10
PMIC_PGOOD: R23.2 R768.1 R769.1 TP40.1 U2.2(A)
PMIC_PWR_EN: R18.1 R19.1 R859.1 TP34.1 U1.46(PWR_EN) ; also on sheet 10
PMIC_STBY_REQ: Q41.1(BASE) ; also on sheet 10
PMIC_WAKE#: R26.2 U1.40(WAKEUP#) ; also on sheet 10
POR_B: R803.1 TP35.1 ; also on sheet 10 17
PWR_OV_BASE: Q2.1(BASE) R4.1
PWR_OV_CTL: D1.1(K) R1.1 R4.2
PWR_OVP_LED: D2.2(A) Q2.3(COLLECTOR) R8.2
QSPIA_DATA0: U6.A3(NAND_READY#) ; also on sheet 12
QSPIA_DATA1: U6.C5(NAND_CE0#) ; also on sheet 12
QSPIA_DATA2: U6.B5(NAND_CE1#) ; also on sheet 12
QSPIA_DATA3: U6.A4(NAND_CLE) ; also on sheet 12
QSPIA_SCLK: R809.2 ; also on sheet 12
QSPIA_SS0#: U6.E6(NAND_DQS) ; also on sheet 12
REV_CHANGE: R814.2 R815.2 U6.L14(GPIO1_IO02)
SD1_CLK: C93.1 R81.2 ; also on sheet 12
SD1_CLK_R: R81.1 U6.C1(SD1_CLK)
SD1_CMD: R72.2 R82.2 ; also on sheet 12
SD1_CMD_R: R82.1 U6.C2(SD1_CMD)
SD1_DATA0: R73.2 U6.B3(SD1_DATA0) ; also on sheet 12
SD1_DATA1: R74.2 U6.B2(SD1_DATA1) ; also on sheet 12
SD1_DATA2: R75.2 U6.B1(SD1_DATA2) ; also on sheet 12
SD1_DATA3: R76.2 U6.A2(SD1_DATA3) ; also on sheet 12
SD1_VSEL: R33.1 R35.1 R37.1 U4.B1(SEL)
SD2_CLK: R71.2 ; also on sheet 11
SD2_CMD: U6.C8(NAND_WE#) ; also on sheet 11
SD2_DATA0: U6.D7(NAND_DATA00) ; also on sheet 11
SD2_DATA1: U6.B7(NAND_DATA01) ; also on sheet 11
SD2_DATA2: U6.A7(NAND_DATA02) ; also on sheet 11
SD2_DATA3: U6.D6(NAND_DATA03) ; also on sheet 11
SD2_DATA4: U6.C6(NAND_DATA04) ; also on sheet 11
SD2_DATA5: U6.B6(NAND_DATA05) ; also on sheet 11
SD2_DATA6: U6.A6(NAND_DATA06) ; also on sheet 11
SD2_DATA7: U6.A5(NAND_DATA07) ; also on sheet 11
SD2_RESET#: U6.B4(NAND_ALE) ; also on sheet 11
SD_VSEL_R: R33.2 U6.D1(CSI_DATA07)
ST_QSPIA_SCLK: R809.1 U6.D5(NAND_WP#)
ST_SD2_CLK: R71.1 U6.D8(NAND_RE#)
STBY_REQ: Q41.3(COLLECTOR) R763.1 U1.26(GPIO3)
SYS_BU: C33.1 U1.24(SYS_BU)
TOUCH_CLOCK: U6.E4(CSI_DATA00) ; also on sheet 19
TOUCH_CS#: U6.E3(CSI_DATA01) ; also on sheet 19
TOUCH_MISO: U6.E1(CSI_DATA03) ; also on sheet 19
TOUCH_MOSI: U6.E2(CSI_DATA02) ; also on sheet 19
USB_HOST_DN: U6.T13(USB_OTG2_DN) ; also on sheet 14
USB_HOST_DP: U6.U13(USB_OTG2_DP) ; also on sheet 14
USB_HOST_ID: R770.2 U6.M17(GPIO1_IO05)
USB_LDO_DECAP: C97.1 C98.1 U6.R12(VDD_USB_CAP)
USB_OTG1_CHD#: TP33.1 U6.U16(USB_OTG1_CHD#)
USB_OTG1_DN: U6.T15(USB_OTG1_DN) ; also on sheet 15
USB_OTG1_DP: U6.U15(USB_OTG1_DP) ; also on sheet 15
USB_OTG1_FAULT#: R86.2 U6.L15(GPIO1_IO01) ; also on sheet 16
USB_OTG1_ID: U6.K13(GPIO1_IO00) ; also on sheet 15
USB_OTG1_PWREN: U6.M16(GPIO1_IO04) ; also on sheet 16
USR_BT0: U6.F2(CSI_VSYNC) ; also on sheet 20
USR_BT1: U6.F3(CSI_HSYNC) ; also on sheet 20
USR_LED1: U6.D4(CSI_DATA04) ; also on sheet 20
USR_LED2: U6.D3(CSI_DATA05) ; also on sheet 20
USR_LED3: U6.D2(CSI_DATA06) ; also on sheet 20
WDOG_ANY: U6.M15(GPIO1_IO09) ; also on sheet 10
N20222589: D5.2(A) R7.1
N20248573: R34.1 U4.A1(EN)
N20257520: R62.1 U7.L9(NC)
N20269907: R17.2 R803.2 U2.4(Y)
N20630241: DA8.3(BK) R782.2

Not connected (* = marked no-connect by the designer): U1 28(N/C_1)* 29(N/C_2)* 34(GPO2)*

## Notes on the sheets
sheet 1
- Schematics Drafted in : Allegro Design entry CIS 17.2
- REV
- Revision Notes
- Designer
- Approver
- Date
- A1
- Initial draft
- VVDN
- TI
- 31-01-2020
- A1-01
- 1) Made R13=200E, R14=300E to avoid loading of DCDC6 feedback.
  2) Made R221NM, R248M to make uSDHC1 as  default boot source.
  3) Made R77  NM. So that  SD connector can control SD_CD# state.
  4) Made R23NMSince the PGOOD_BU voltage is of 1V8 and PU is
  3V
  5) Made R250NM, R219M to select 4 bit bus width boot
  6) Made R231NM, R238M to disable powercycle during boot
  7) Made R571NM to disable extender mode in ethernet PHY
  8) Made R773NM, R779NM to avoid the distortion of RMII
  Referance clock.
  9) Made R771 NM to make PMIC_PWR_EN High always
- VVDN
- 17-03-2020
- TI
- TIXU_MX6Y
- A1-02
- 1) R771Mounted
- VVDN
- TI
- 17-03-2020
- Content
- A1-03
- 1) Mounted R190, R191, R261 with 0E; Made R192, R193, R262 NM
  For LCD Rework
- VVDN
- TI
- 20-03-2020
- Page No
- Sheet Name
- 01
- COVER PAGE
- 02
- BLOCK DIAGRAM
- A1-04
- 1) Mounted R773, R779 with 510E for avoiding the dip in referance
  clock voltage.
  2)Mounted R872, R873 with 49.9E and R208, R204 with 47K for
  clearing push button deglitch
- VVDN
- TI
- 26-03-2020
- 03
- DC JACK_MAIN POWER IN
- 04
- PMIC TPS6521815
- A2
- A2 Release
- VVDN
- TI
- 26-03-2020
- 05
- LOAD SWITCH & COINCELL
- 06
- IMX POWER
- 07
- IMX-DDR3L
- 08
- IMX-LCD, ENET, eMMC, SDIO
- 09
- IMX - CSI, USB, ADC, GPIO
- 10
- IMX CONTROL
- 11
- eMMC
- 12
- NOR FLASH & SD CARD
- 13
- ETHERNET PHY
- 14
- USB HUB
- 15
- USB_OTG_HOST
- 16
- USB CONNECTORS
- 17
- USB-UART_USB2ANY_JTAG
- 18
- CURRENT SENSE
- 19
- LCD
- 20
- BOOT SWITCH, LED AND GPIO
- 21
- MISCELLANEOUS
- TIDA-050043
sheet 2
- BLOCK DIAGRAM
- POWER ARCHITECTURE
sheet 3
- DC JACK (Main Power IN)
- Note: Over-voltage protection is designed to withstand up to +20V.
- OVER VOLTAGE INDICATOR
- PMIC Input Power LED (GREEN) Indication
sheet 4
- PMIC TPS6521815
- Output Capacitor for all the power rails -
  Place near the output Inductor/ Pins
- Input Capacitor for power rails -
  Place near U1 pins 1, 43, 37,12
- Input Capacitor for power rails -
  Place near U1 pins 5, 31, 32, 6, 27
- The voltage range of SNVS_IN
  can be 2.4V to 3.6V
- NM
- NM
- POR Logic
- PFI set for a threshold of 3.5V
- PULL UP RES
- PMIC PB
- NM
- NM
- NM
- If R843 Mounted
  Voltage to
  processor will be
  3.43V
- GPIO1/3, PGOOD, INT#, WAKEUP#, PFO# Configured
  as Open Drain
sheet 5
- LOAD SWITCH & COINCELL
- VDD_PERI_3V3 SWITCH (LS5)
- COIN CELL
- Remove DCDC6 connection to
  VDD_SNVS_IN if we use this option
- Make the status of GPIO1 low before
  the power up
- NM
- NM
- SD CARD VOLTAGE SELECTION SWITCH
- NM
- NM
- 5V LOAD SWITCH (LS4)
- Please mount all 3 res together in case of using this option
- NM
- NM
sheet 6
- i.MX6ULL POWER
- Place 22 uF cap and one of the 0.22uF
  caps next to the ball G9. Place others
  within 50 mils of via. Do not connect
  any loads to VDDARM_CAP.
- Place 22 uF cap and one of the 0.22uF
  caps next to the ball K10.
- Place 22 uF cap and one of the 0.22uF caps
  next to the pin L10. Place others within 50
  mils of via.
- NM
- Diode Is recommended in
  I.MX6ULL Hardware user
  guide
sheet 7
- i.MX6ULL - DDR3L
- NM
- Place the caps closely
- DRAM_VREF GENERATION
- DRAM CLOCK TERMINATION
- Place close to DDR
- Place close to DDR
sheet 8
- IMX-LCD, ENET, eMMC, SDIO
- Place R738 & 739 in tripad
- NM
- 3V3 and 1V8 options are
  given since there is a
  small confusion in data
  sheet
- LCD_WR_RWn
- LCD_RS
- NOR FLASH/
- eMMC
- Place R773 & R779 close to
  processor (Parallel termination)
sheet 9
- IMX - CSI, USB, ADC, GPIO
